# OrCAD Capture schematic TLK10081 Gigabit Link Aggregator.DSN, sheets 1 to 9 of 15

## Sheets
1 S15 BOARD TO BOARD CLOCK: size B
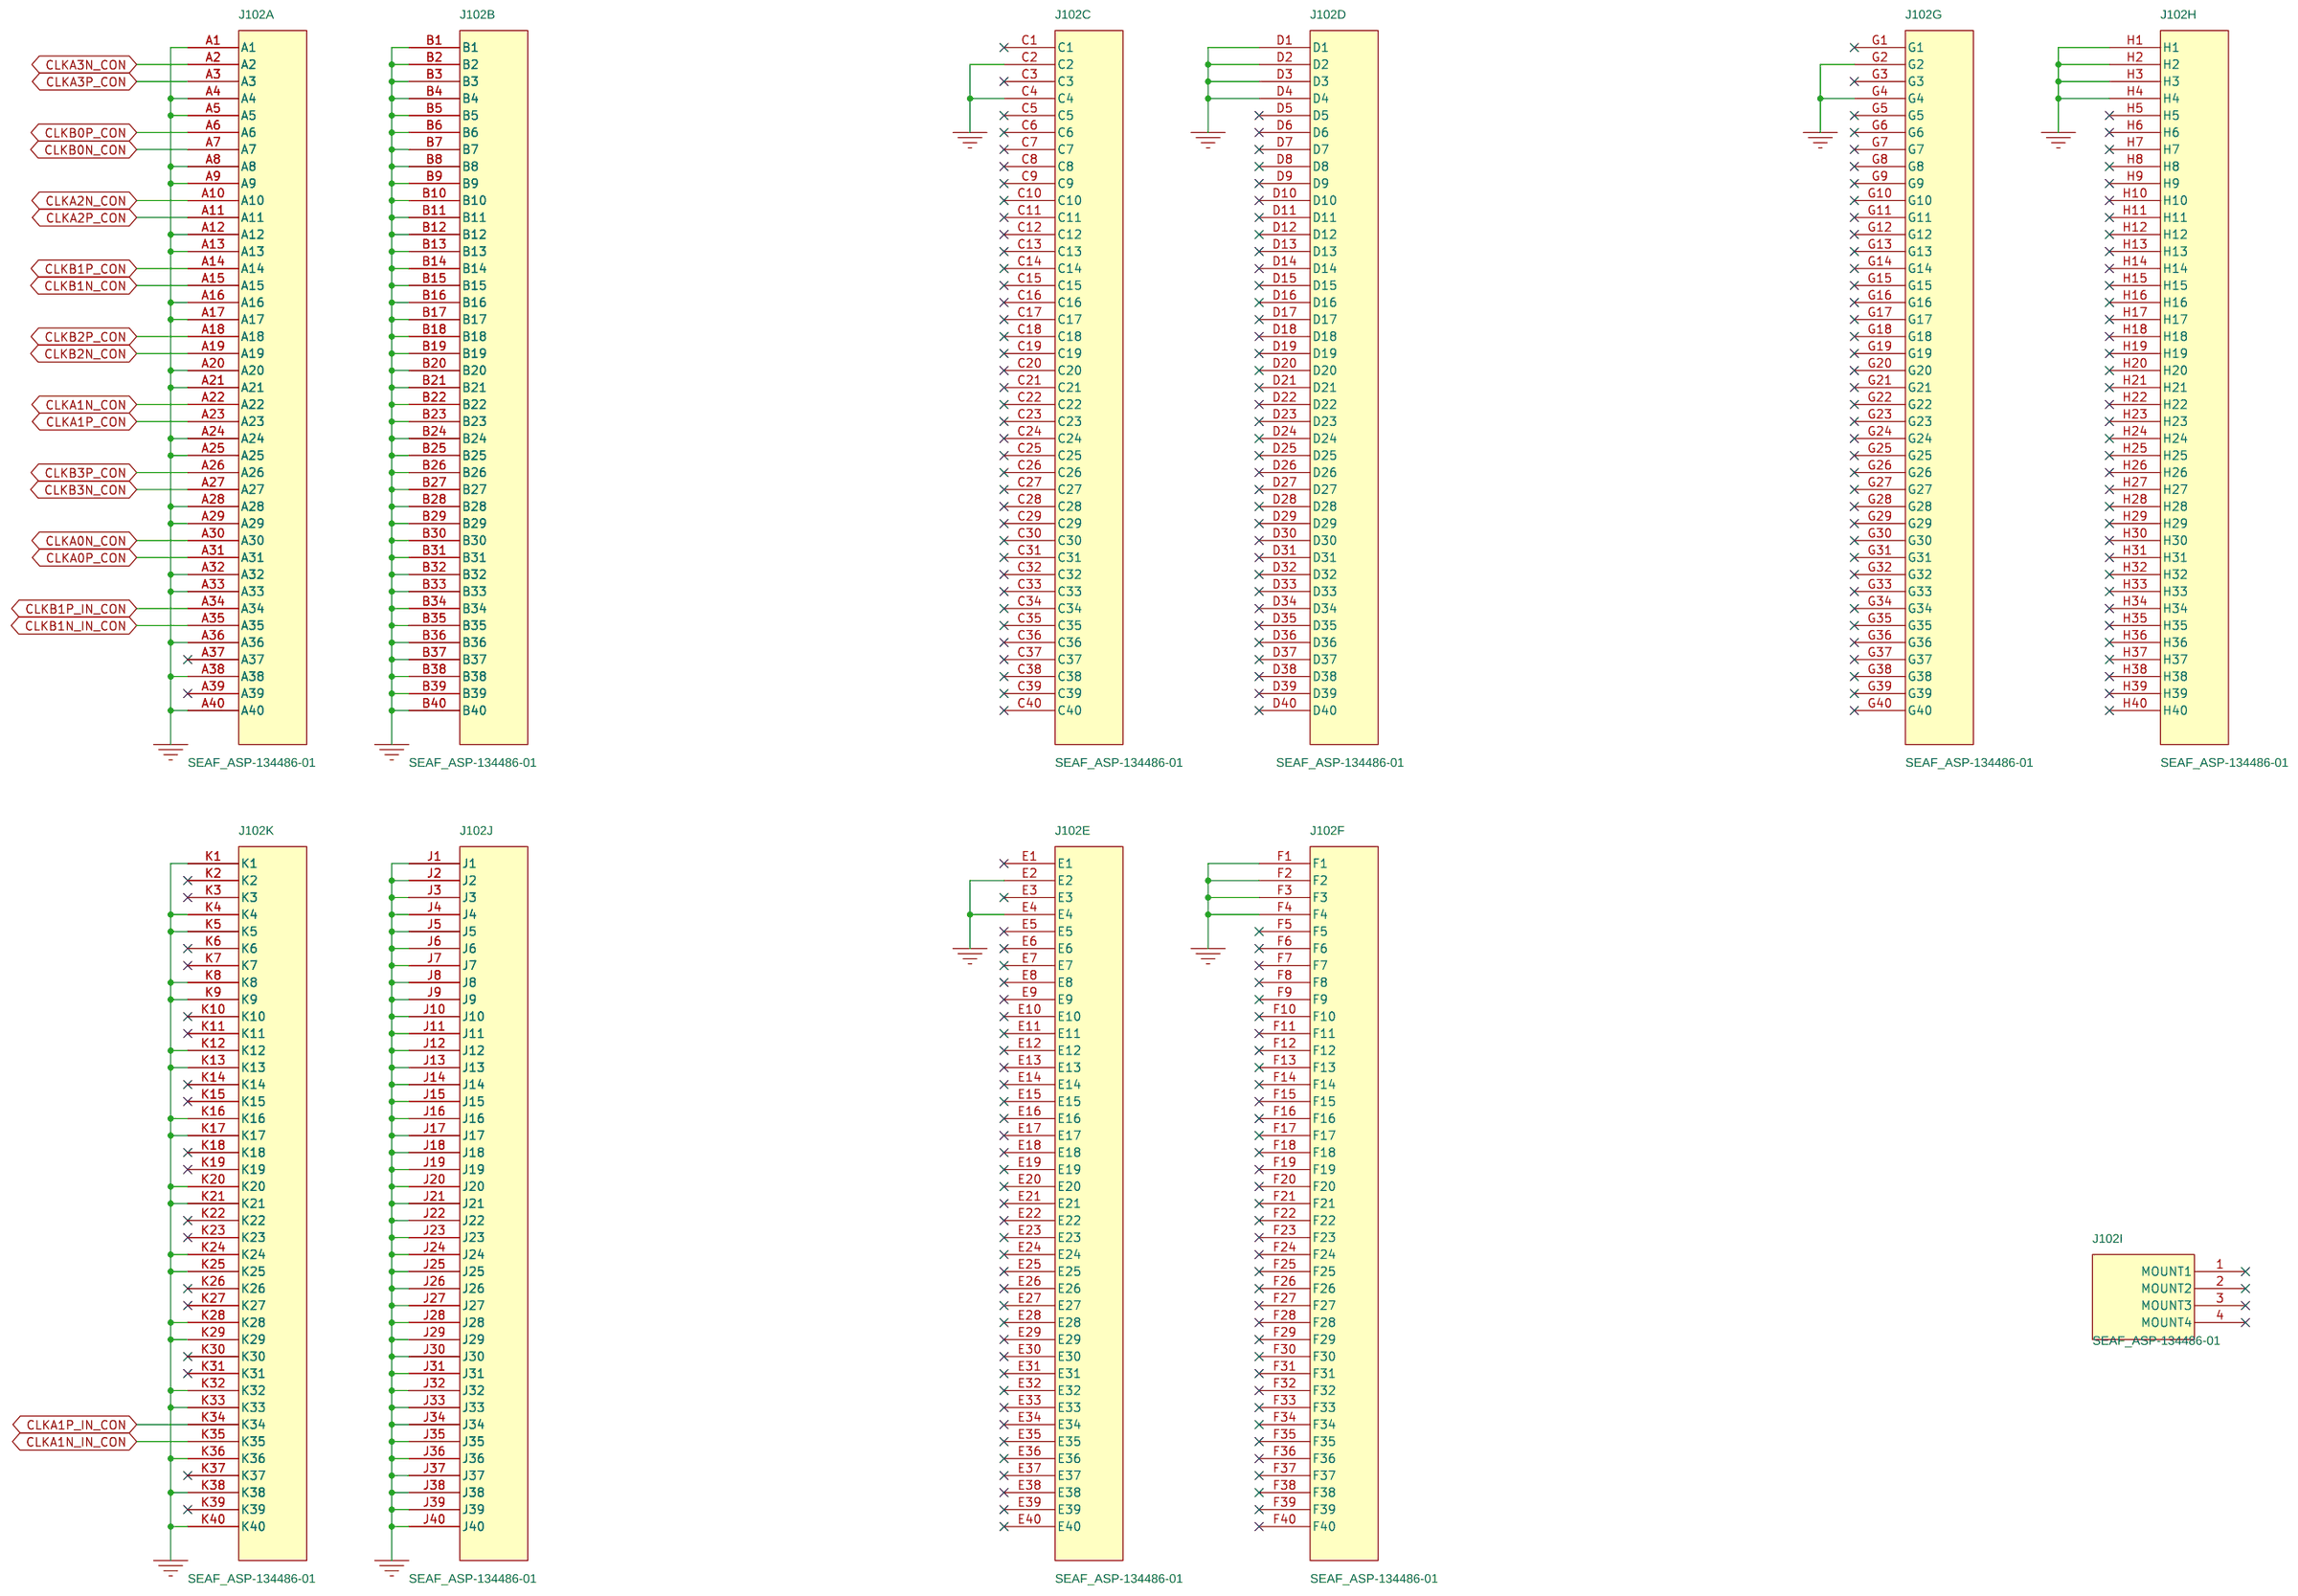
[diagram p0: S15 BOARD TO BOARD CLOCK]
2 S01 TLK10081 EVM COVER PAGE
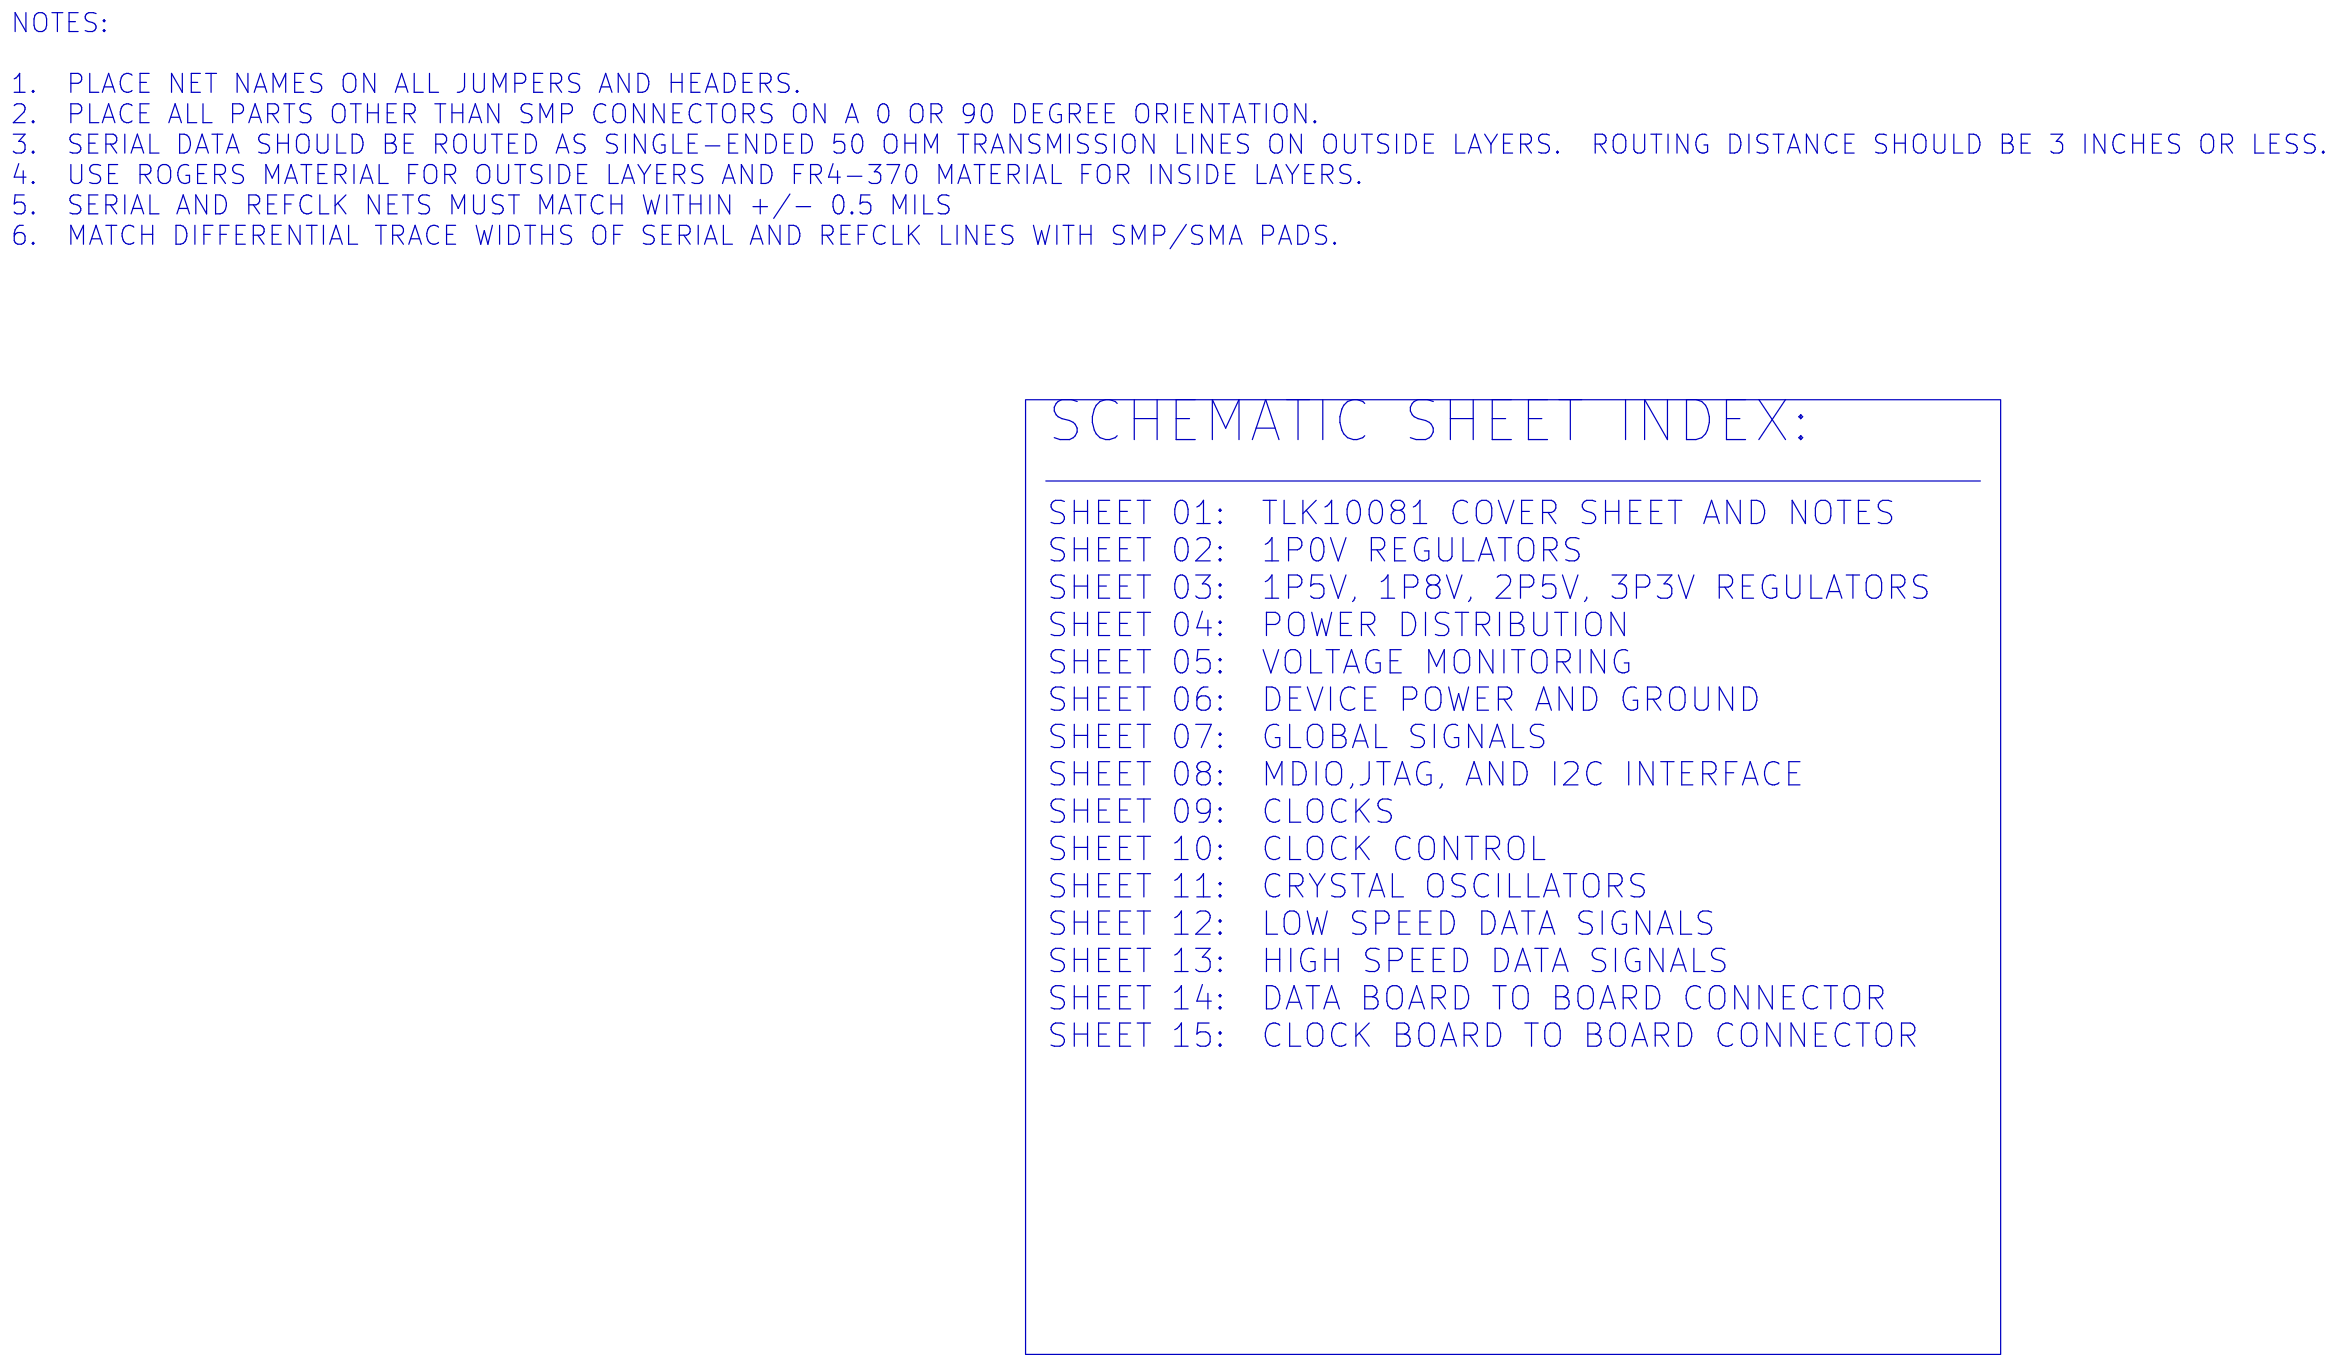
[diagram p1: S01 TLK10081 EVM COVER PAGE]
3 S02 1P0V REGULATORS: size B
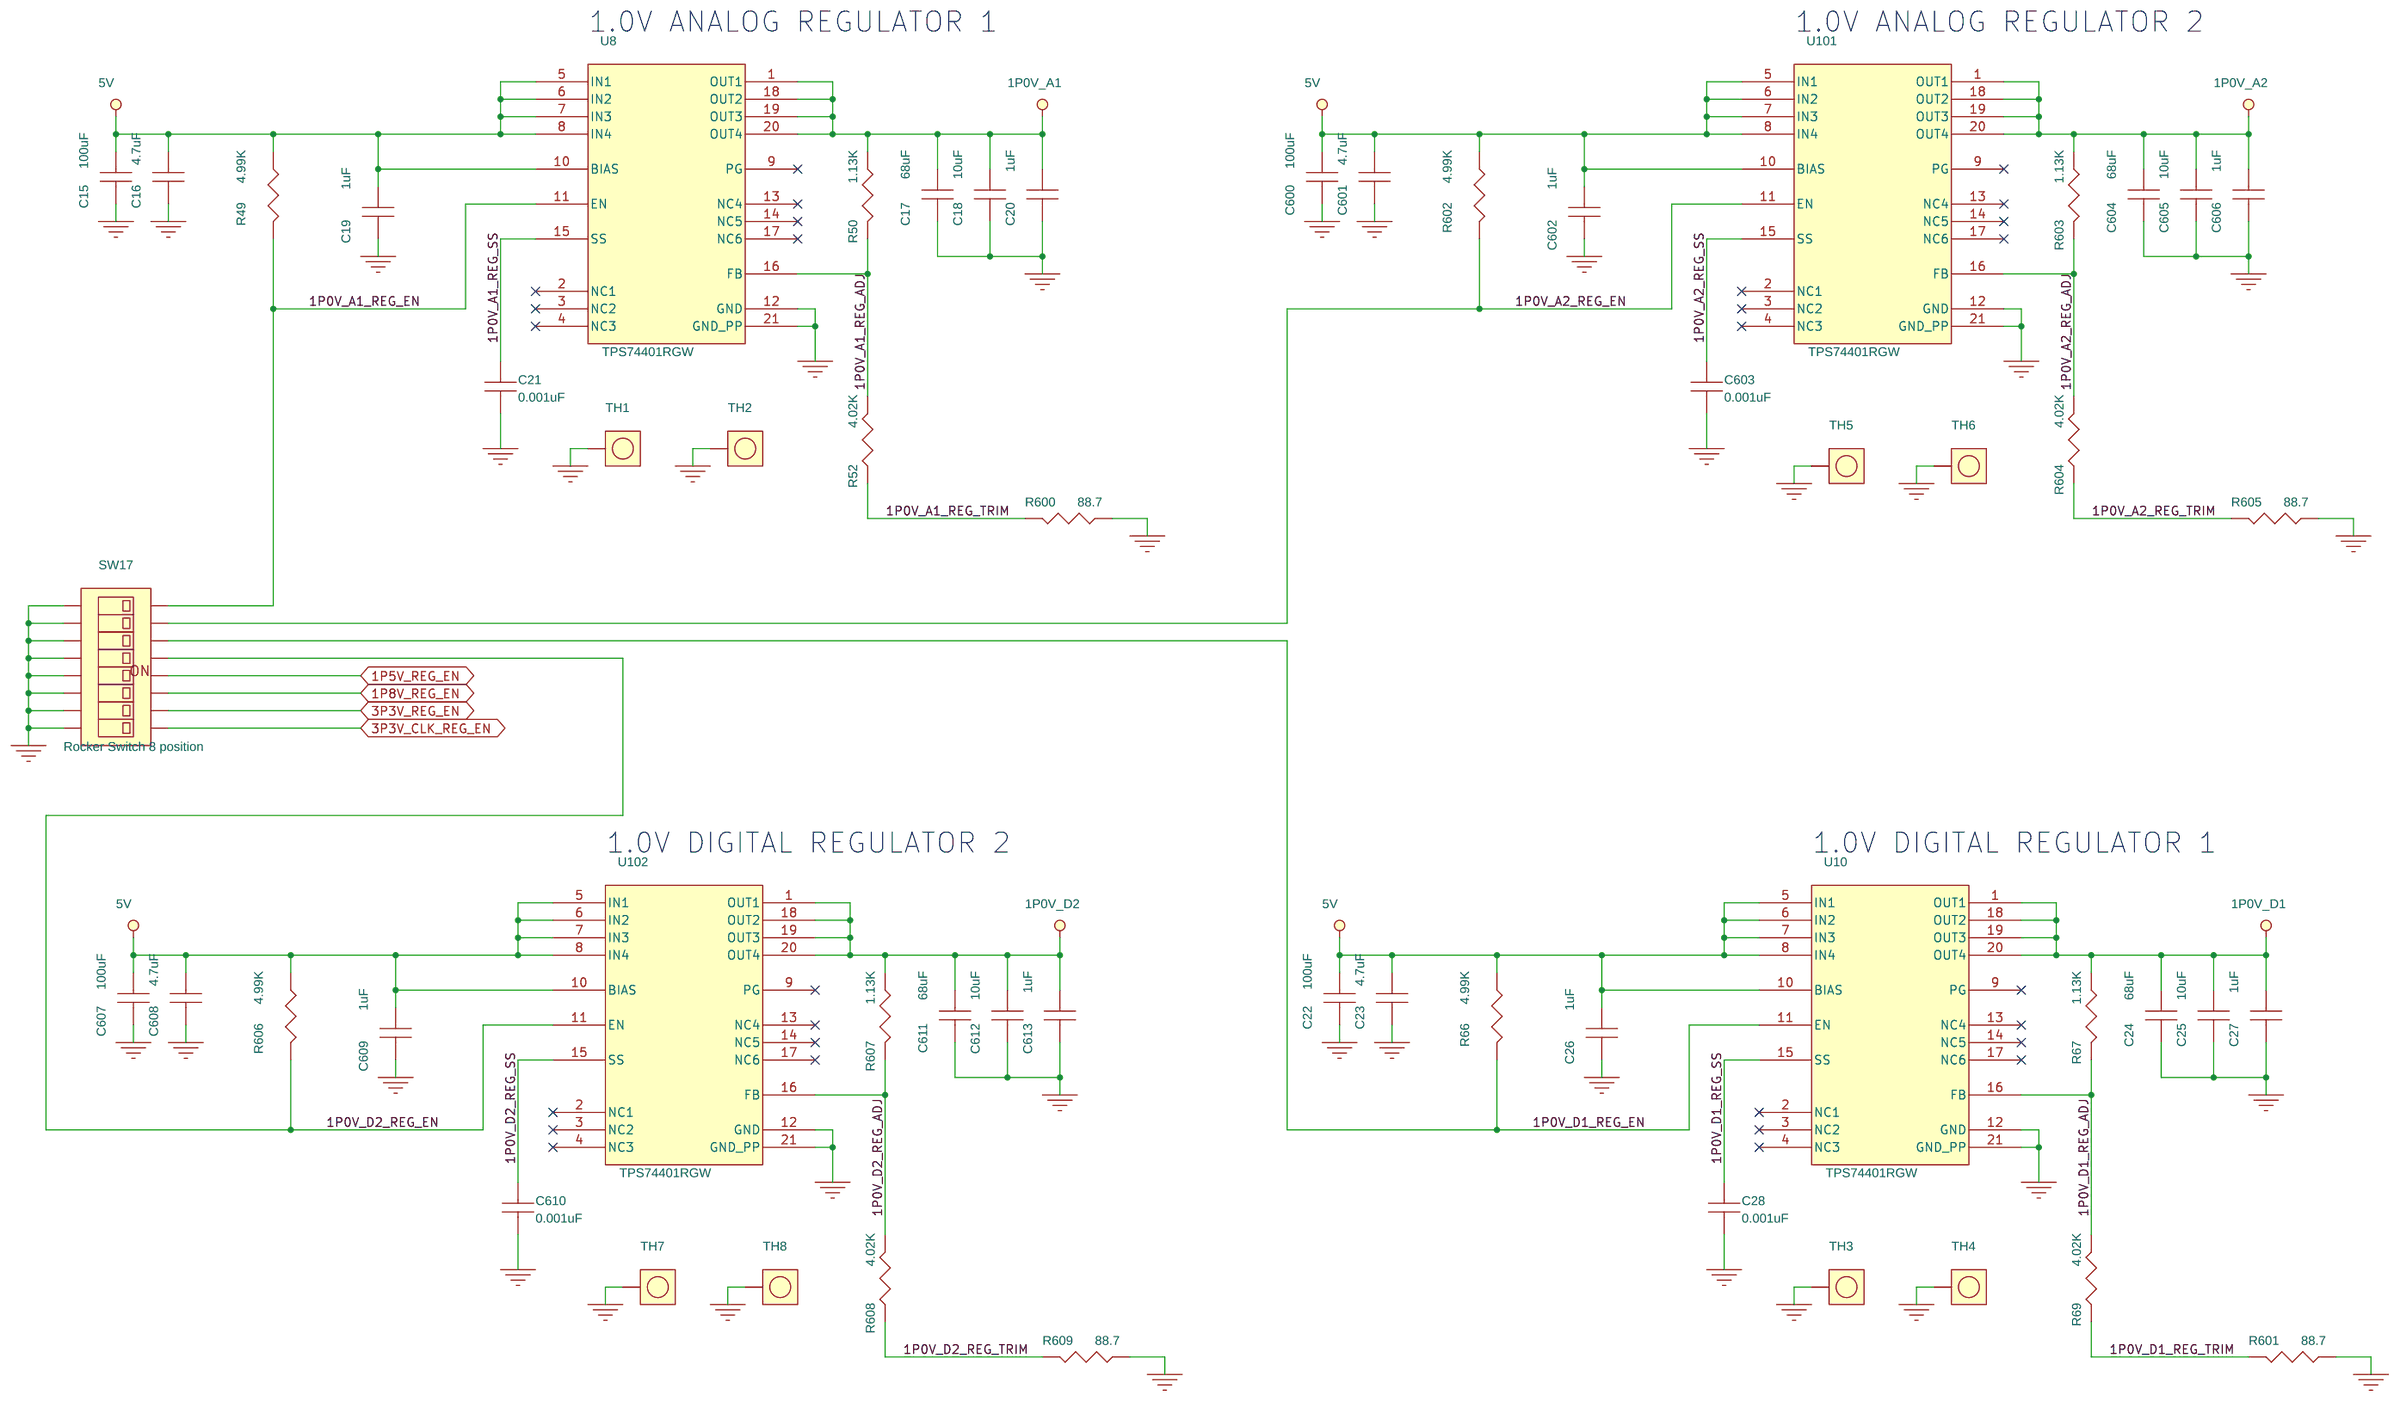
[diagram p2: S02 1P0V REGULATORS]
4 S03 1P5,1P8,2P5,3P3V REGULATORS: size B
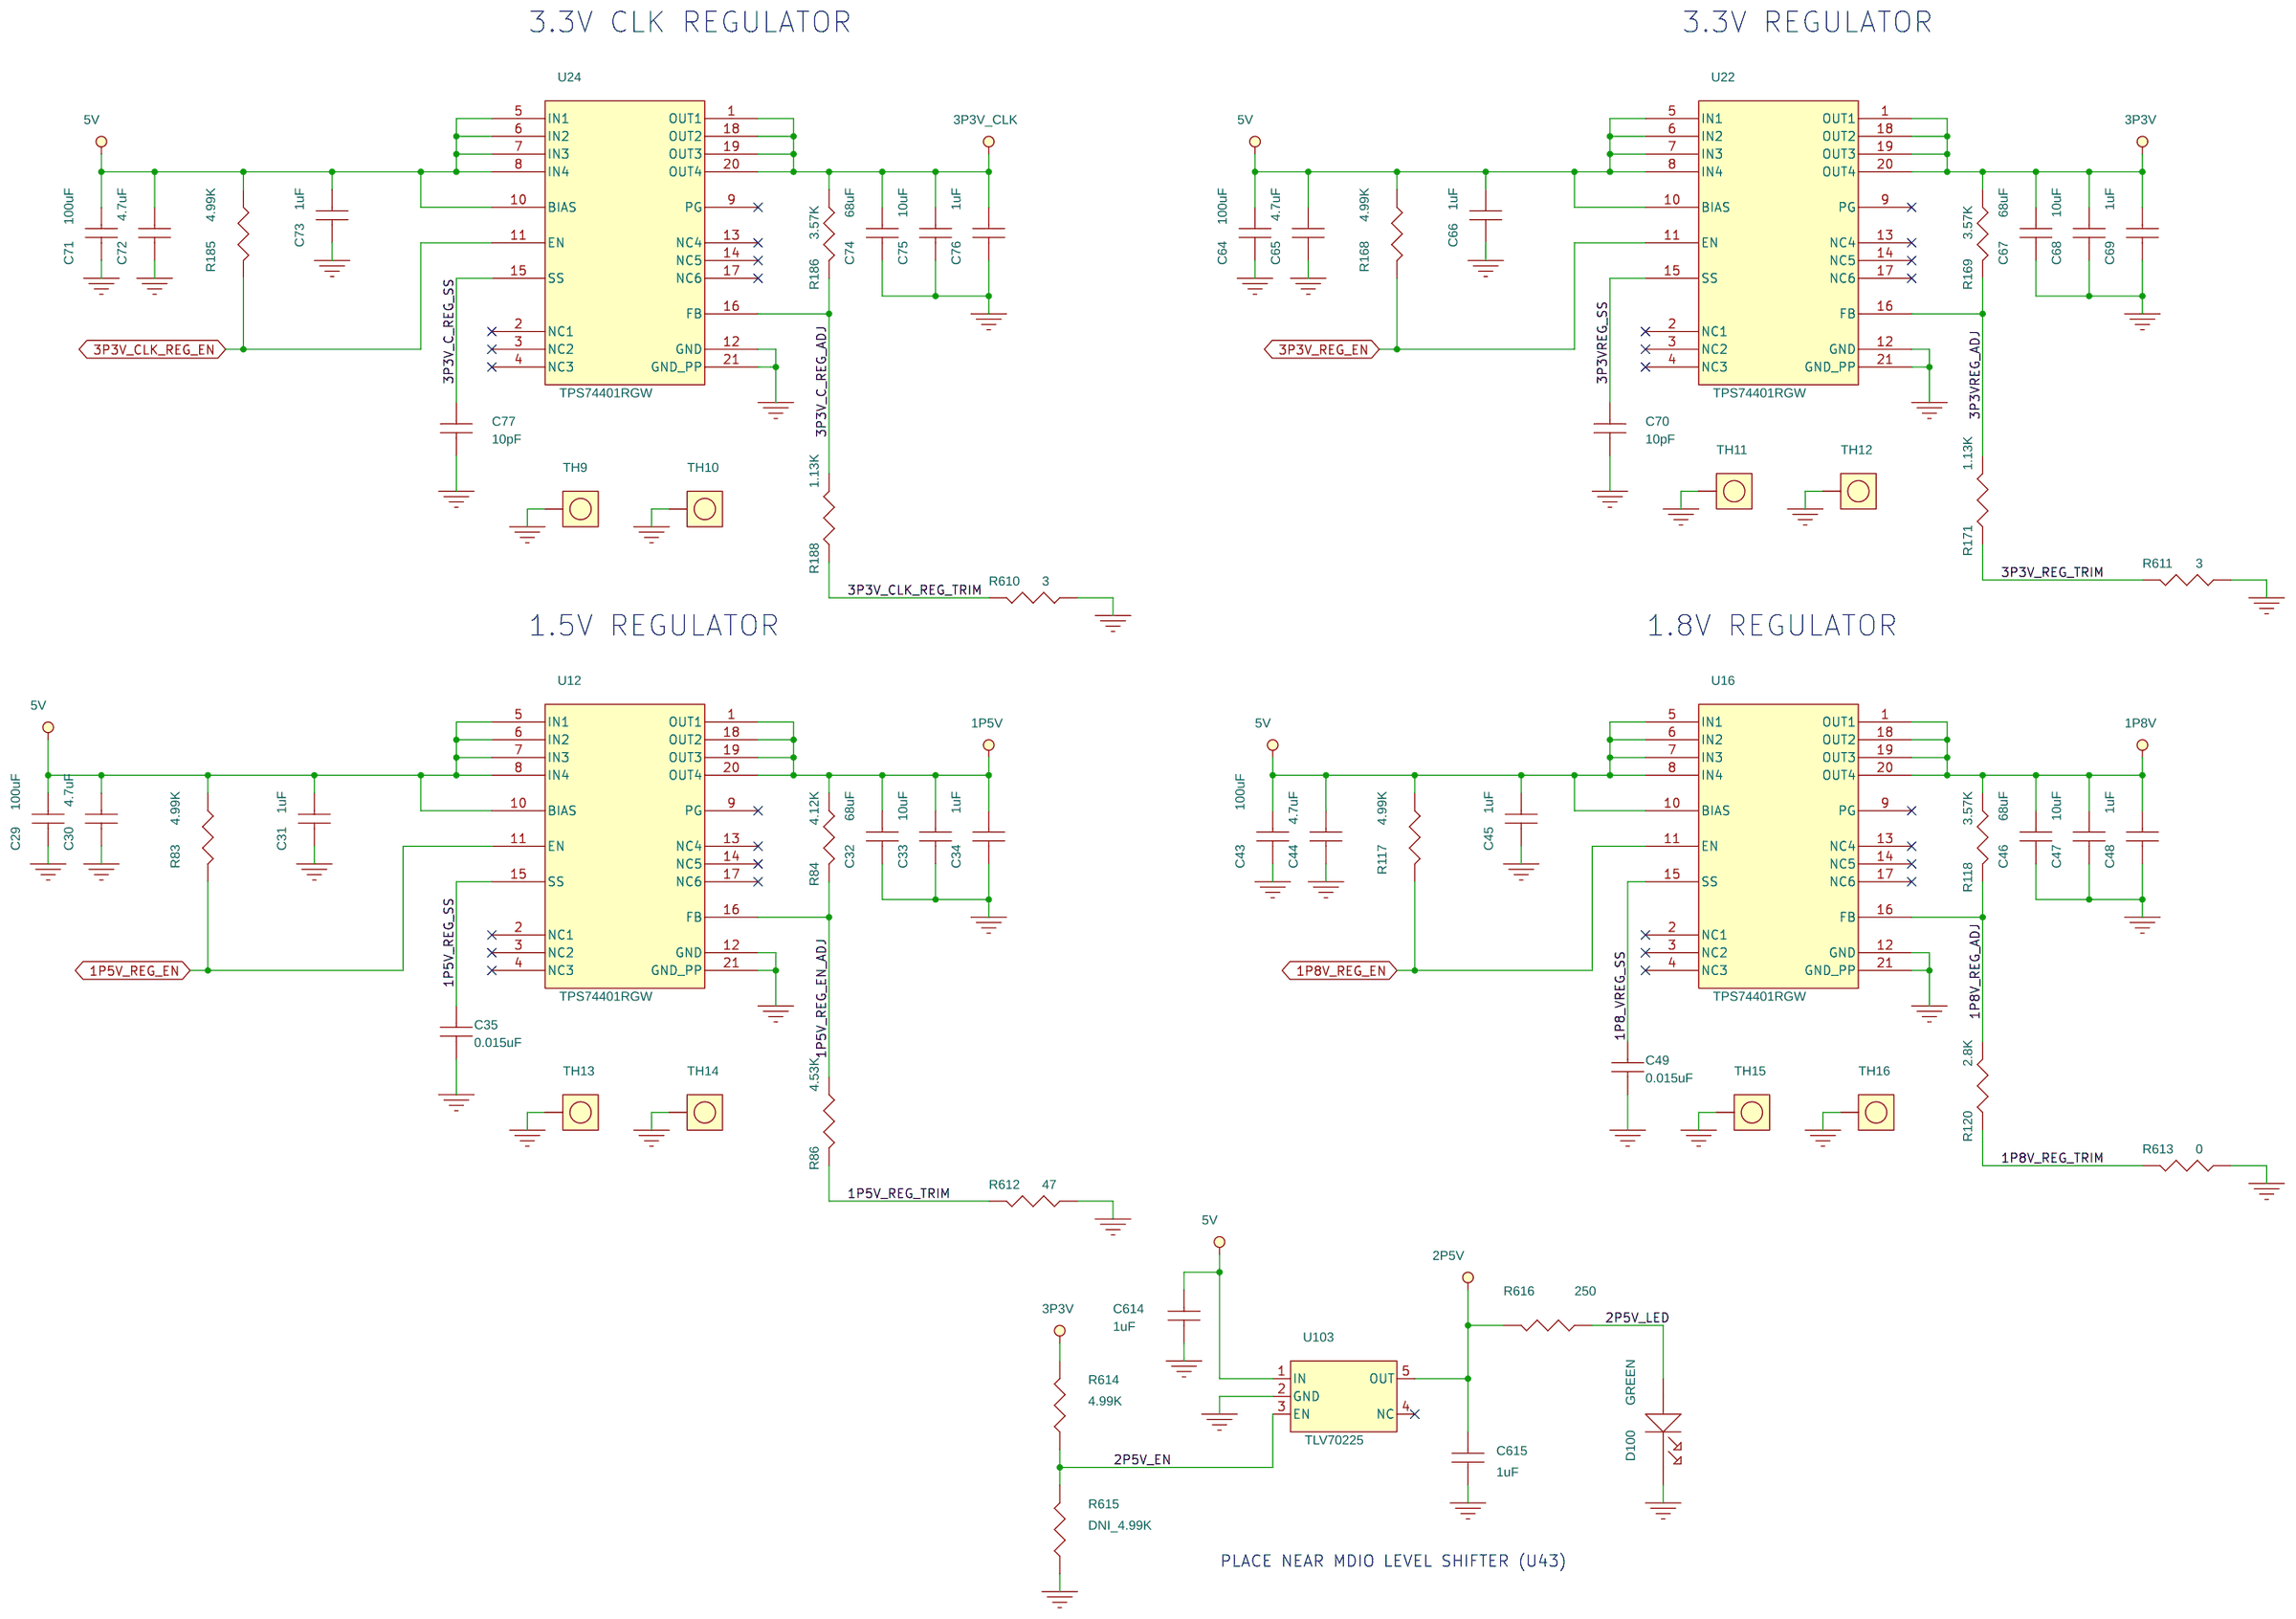
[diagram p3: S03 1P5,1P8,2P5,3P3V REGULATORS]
5 S04 POWER DISTRIBUTION: size B
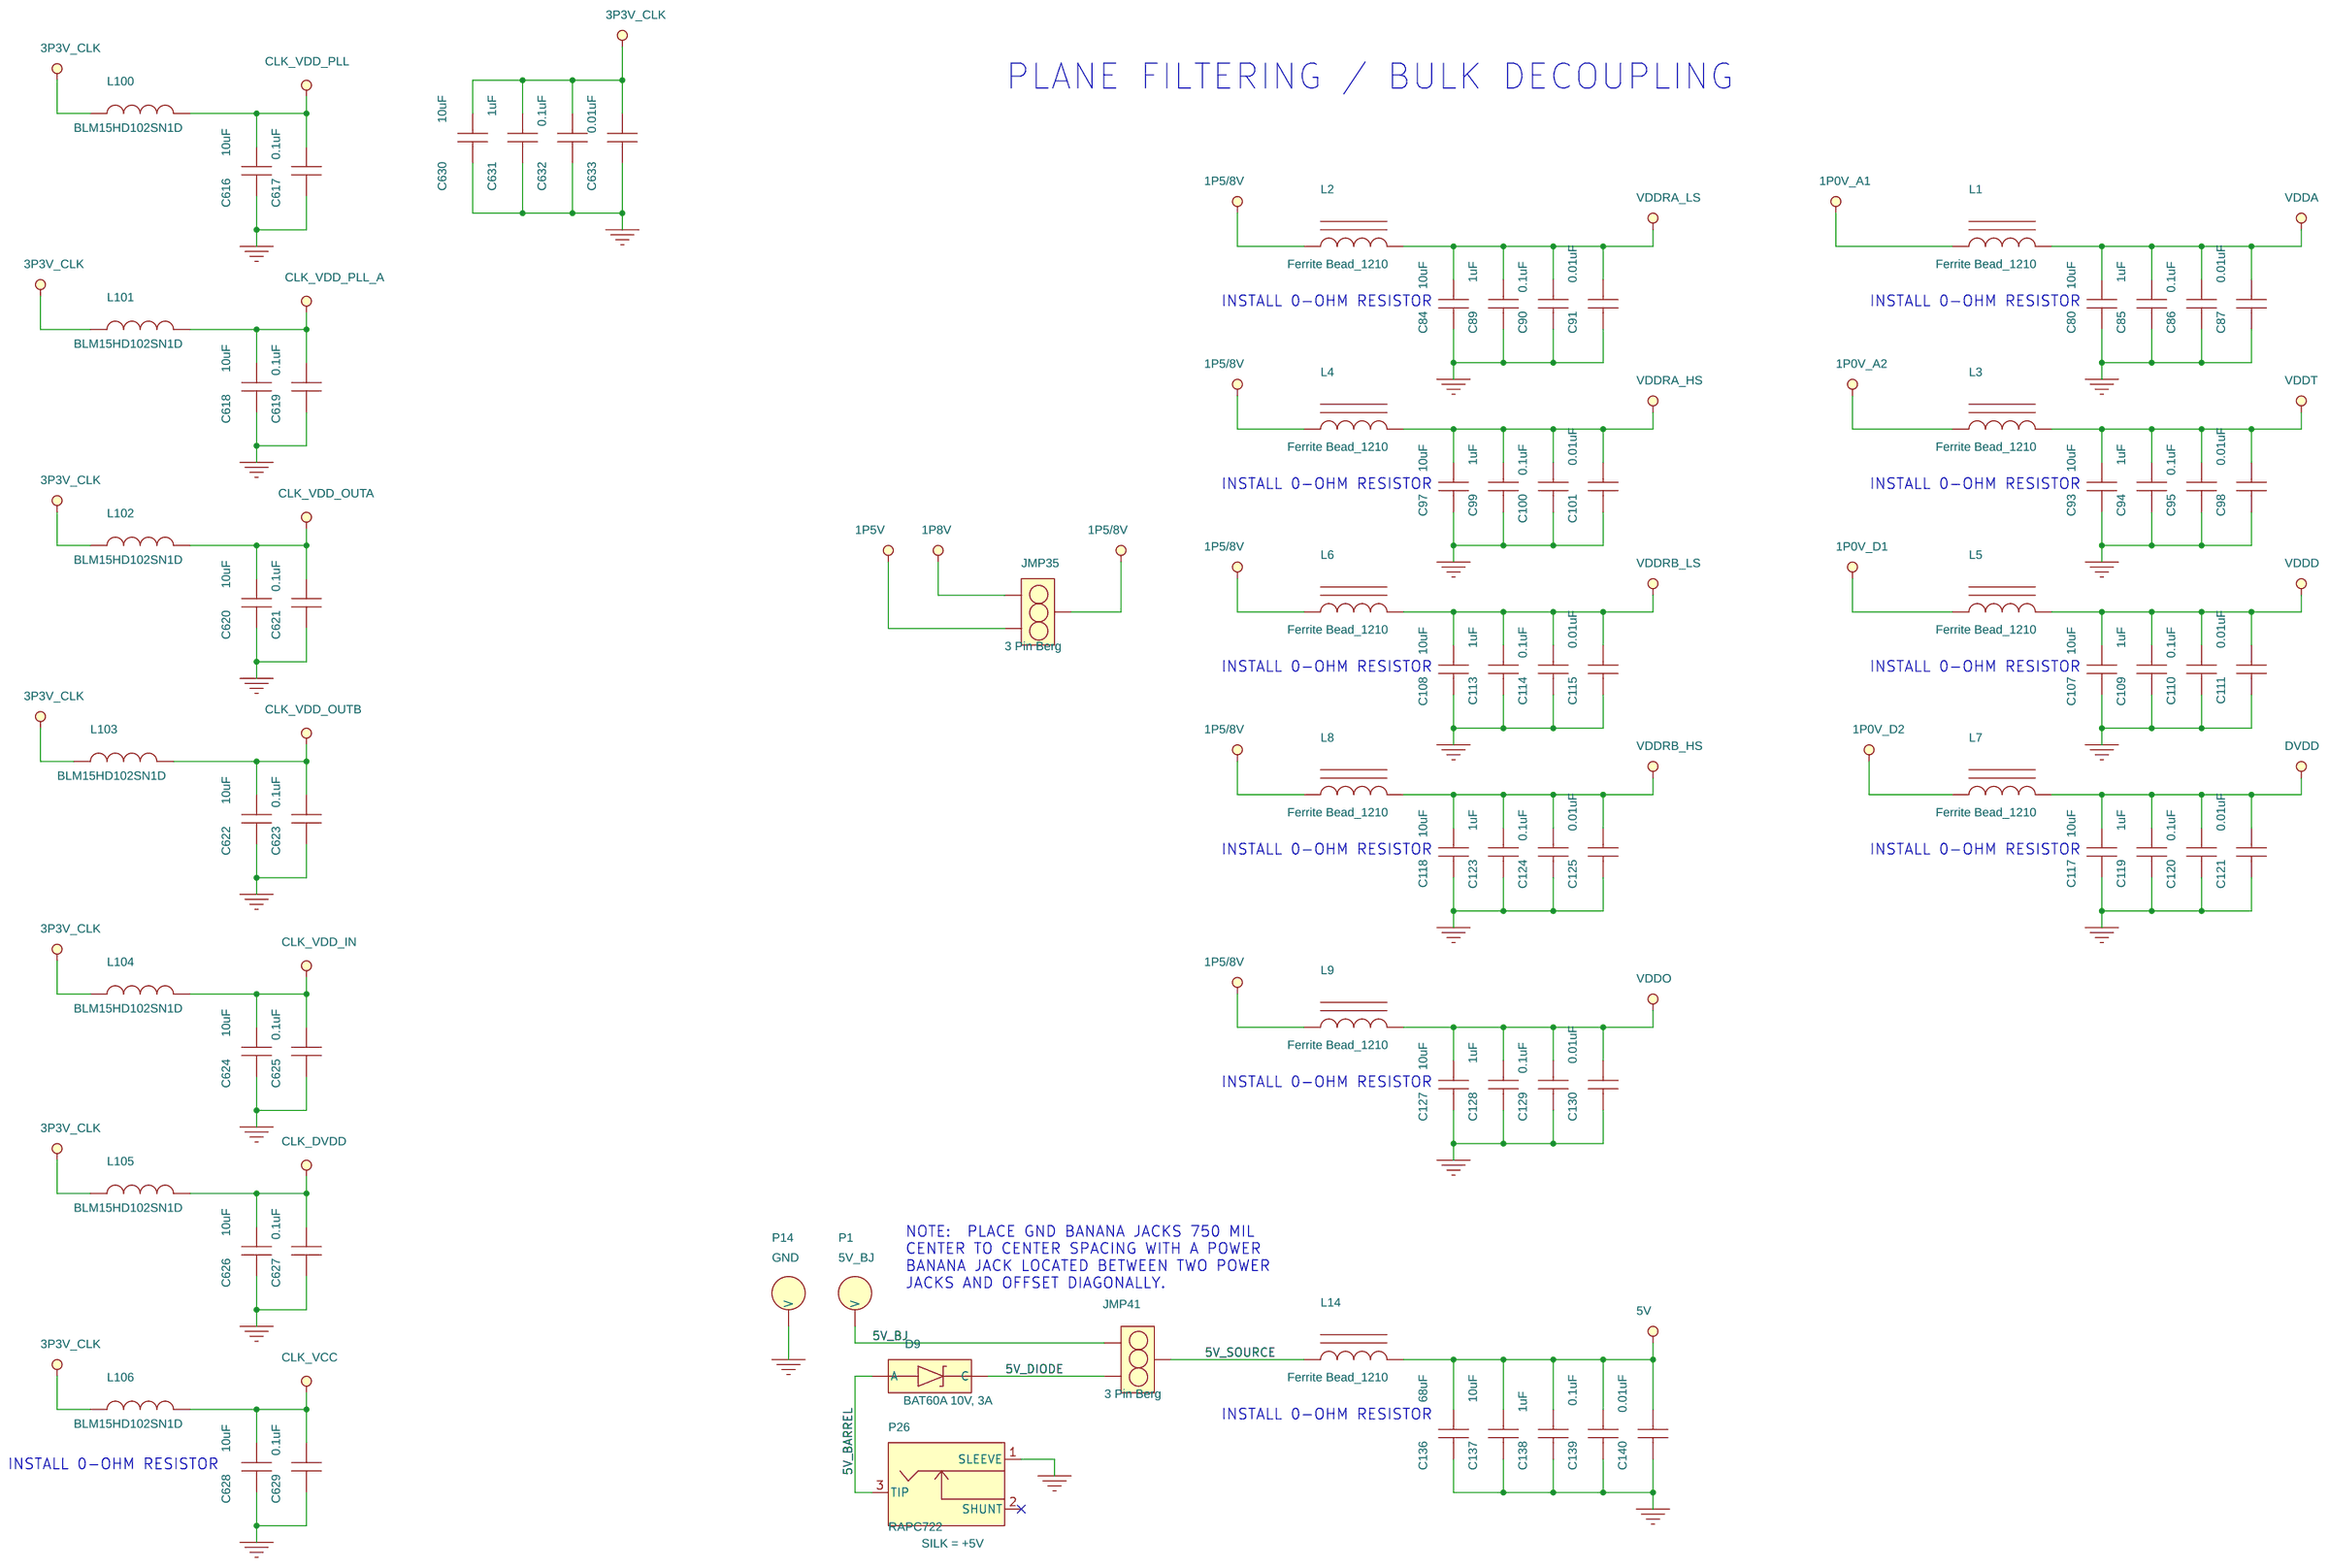
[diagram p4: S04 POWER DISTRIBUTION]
6 S06 DEVICE POWER GROUND: size B
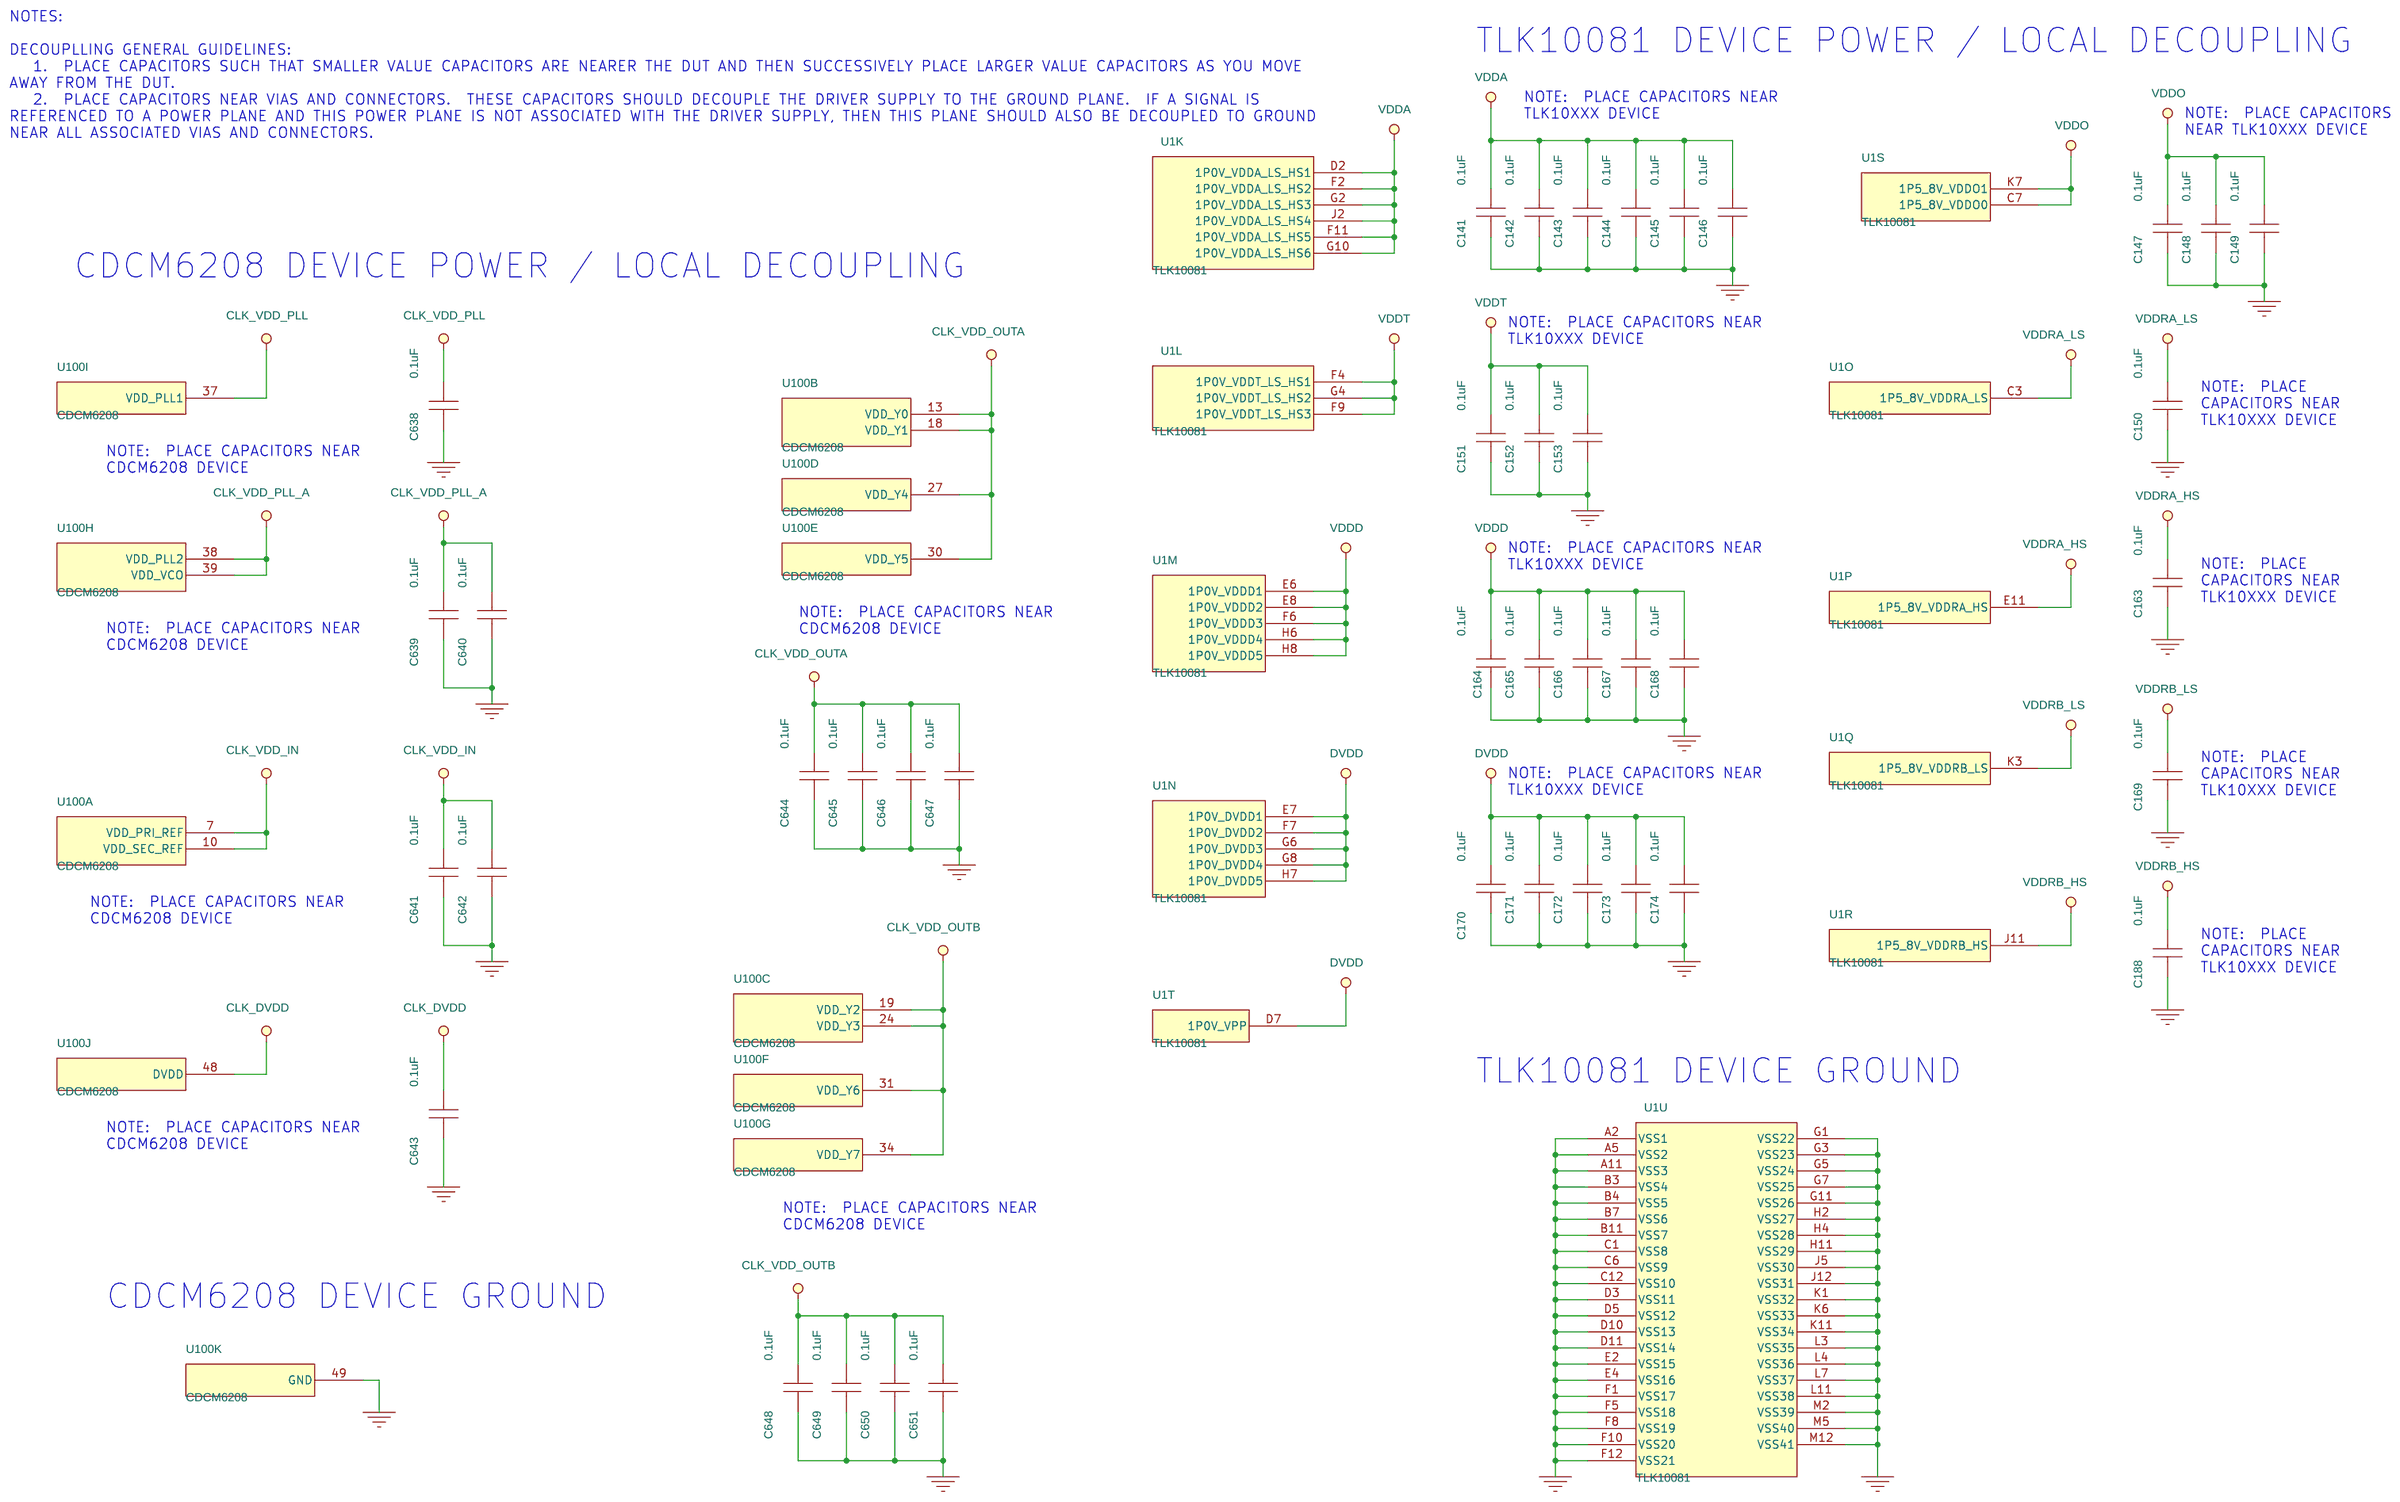
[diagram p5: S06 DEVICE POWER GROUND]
7 S07 GLOBAL SIGNALS: size B
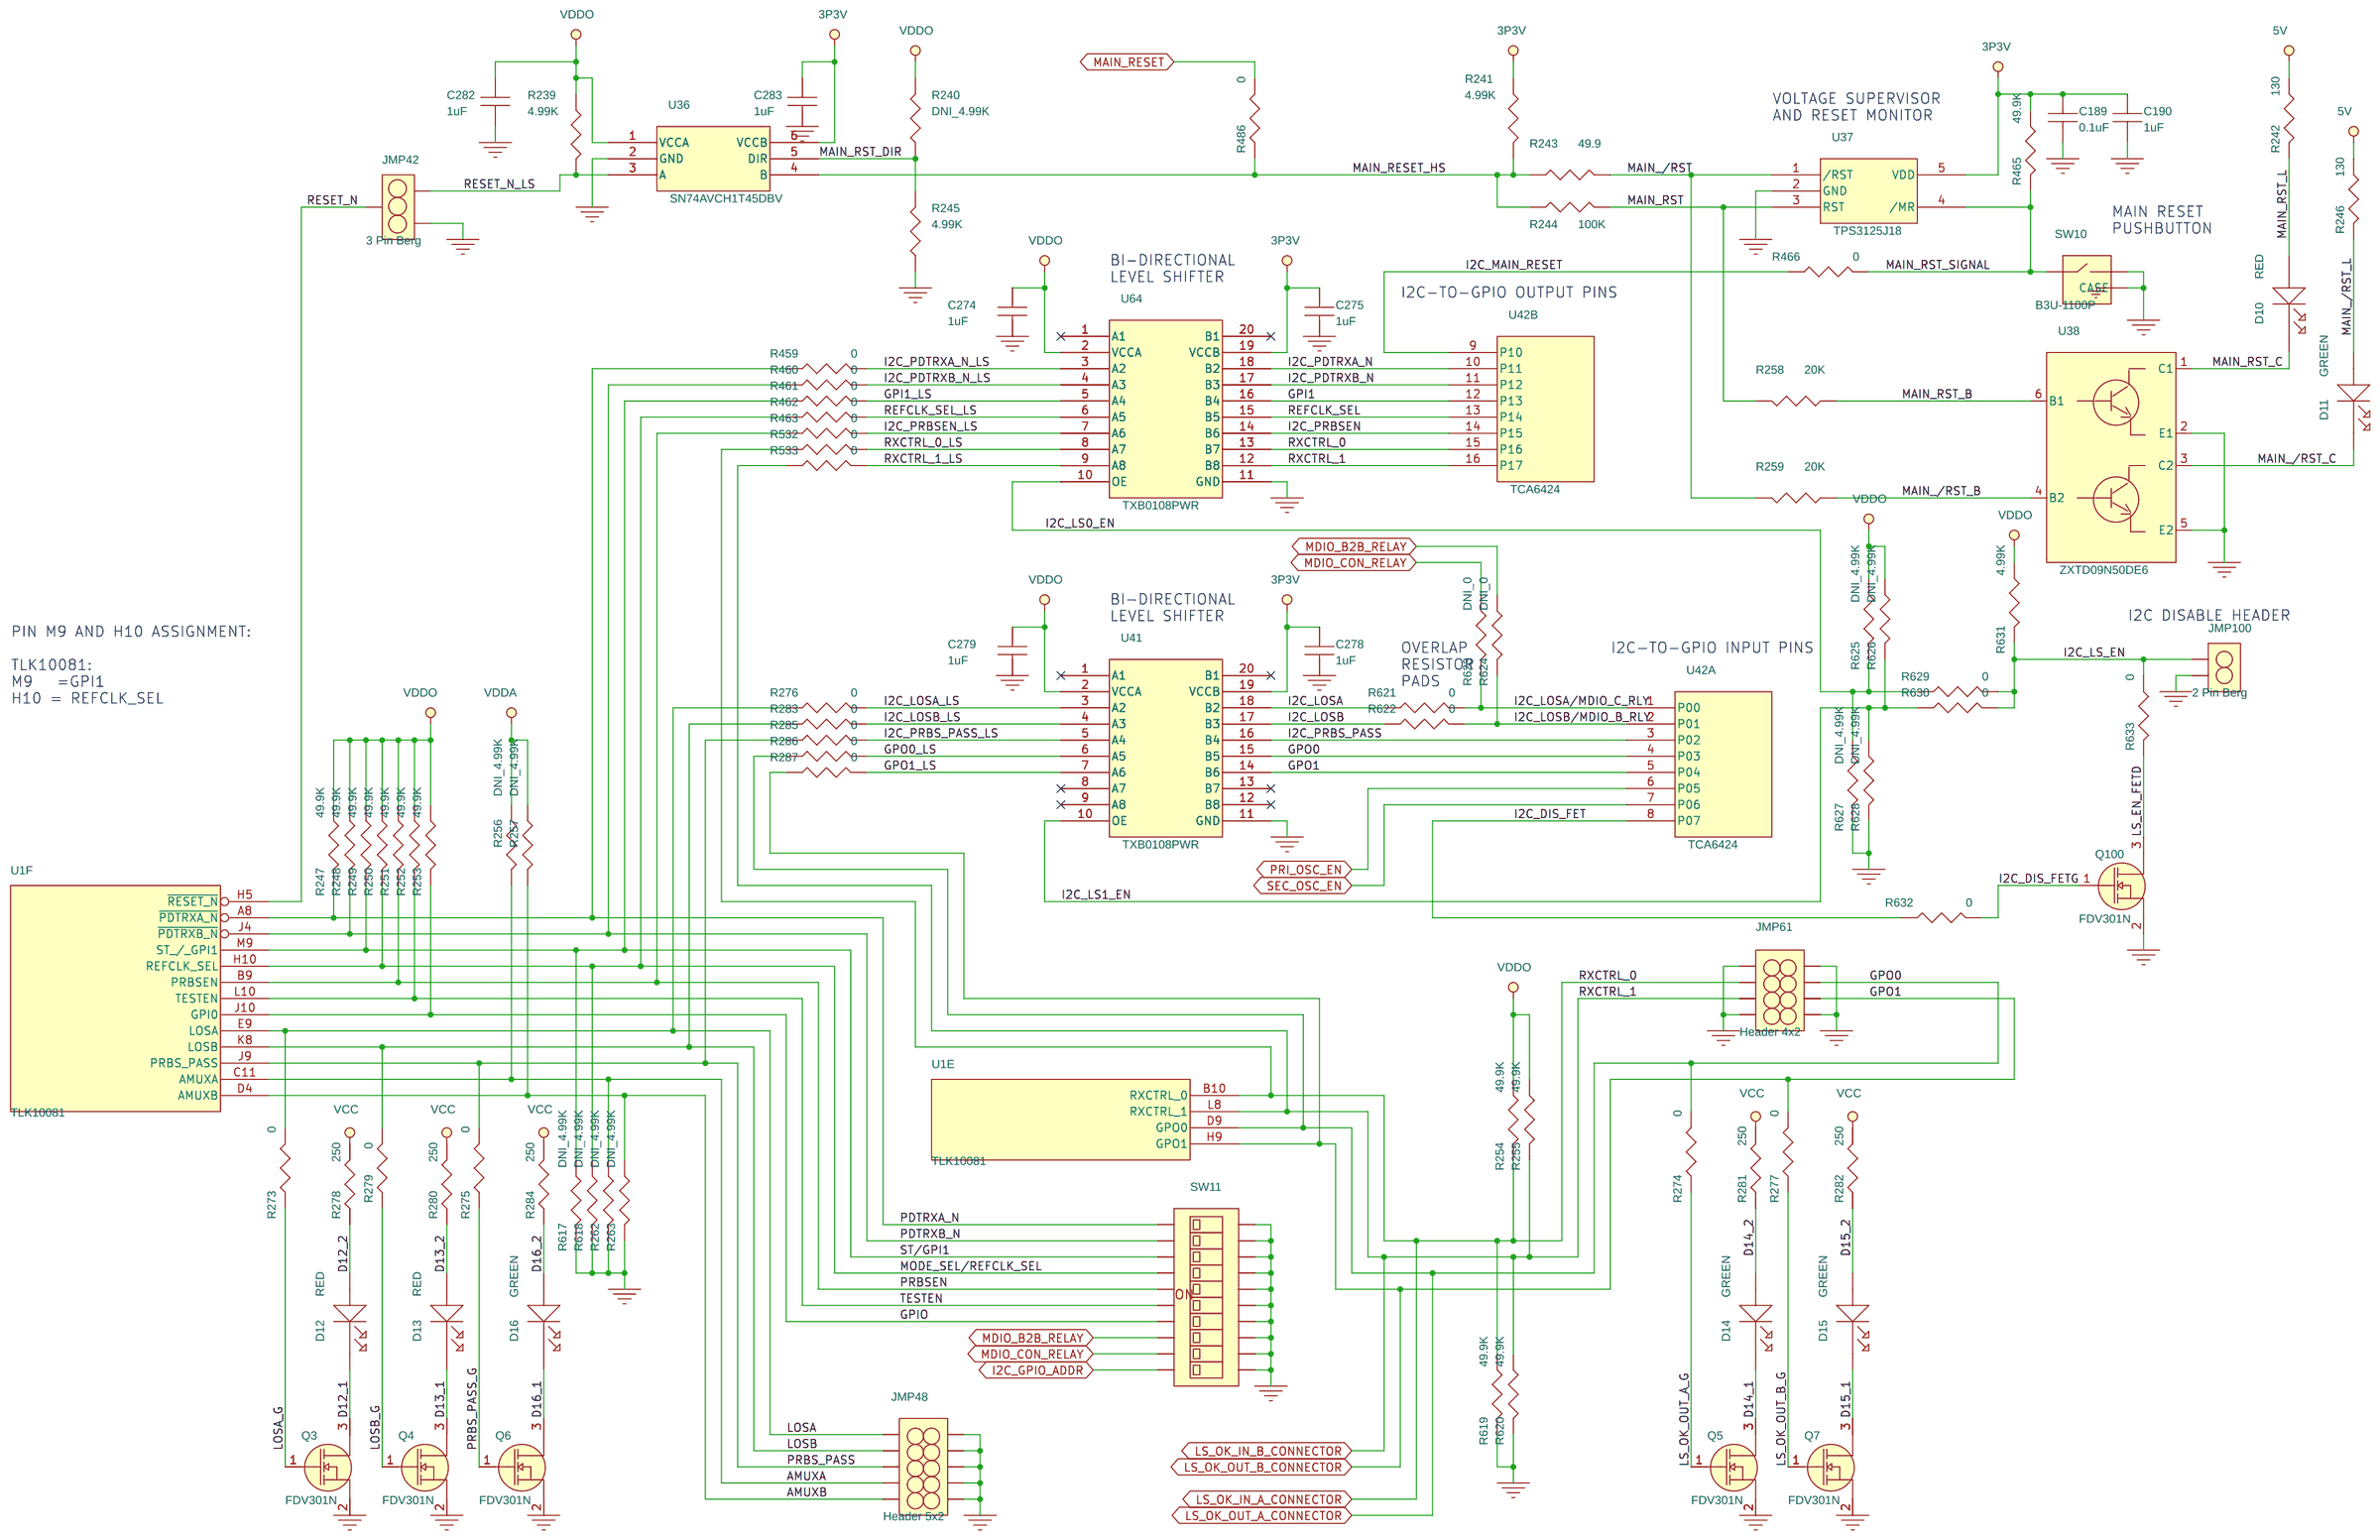
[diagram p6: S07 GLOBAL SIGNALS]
8 S08 MDIO, JTAG, I2C INTERFACE: size B
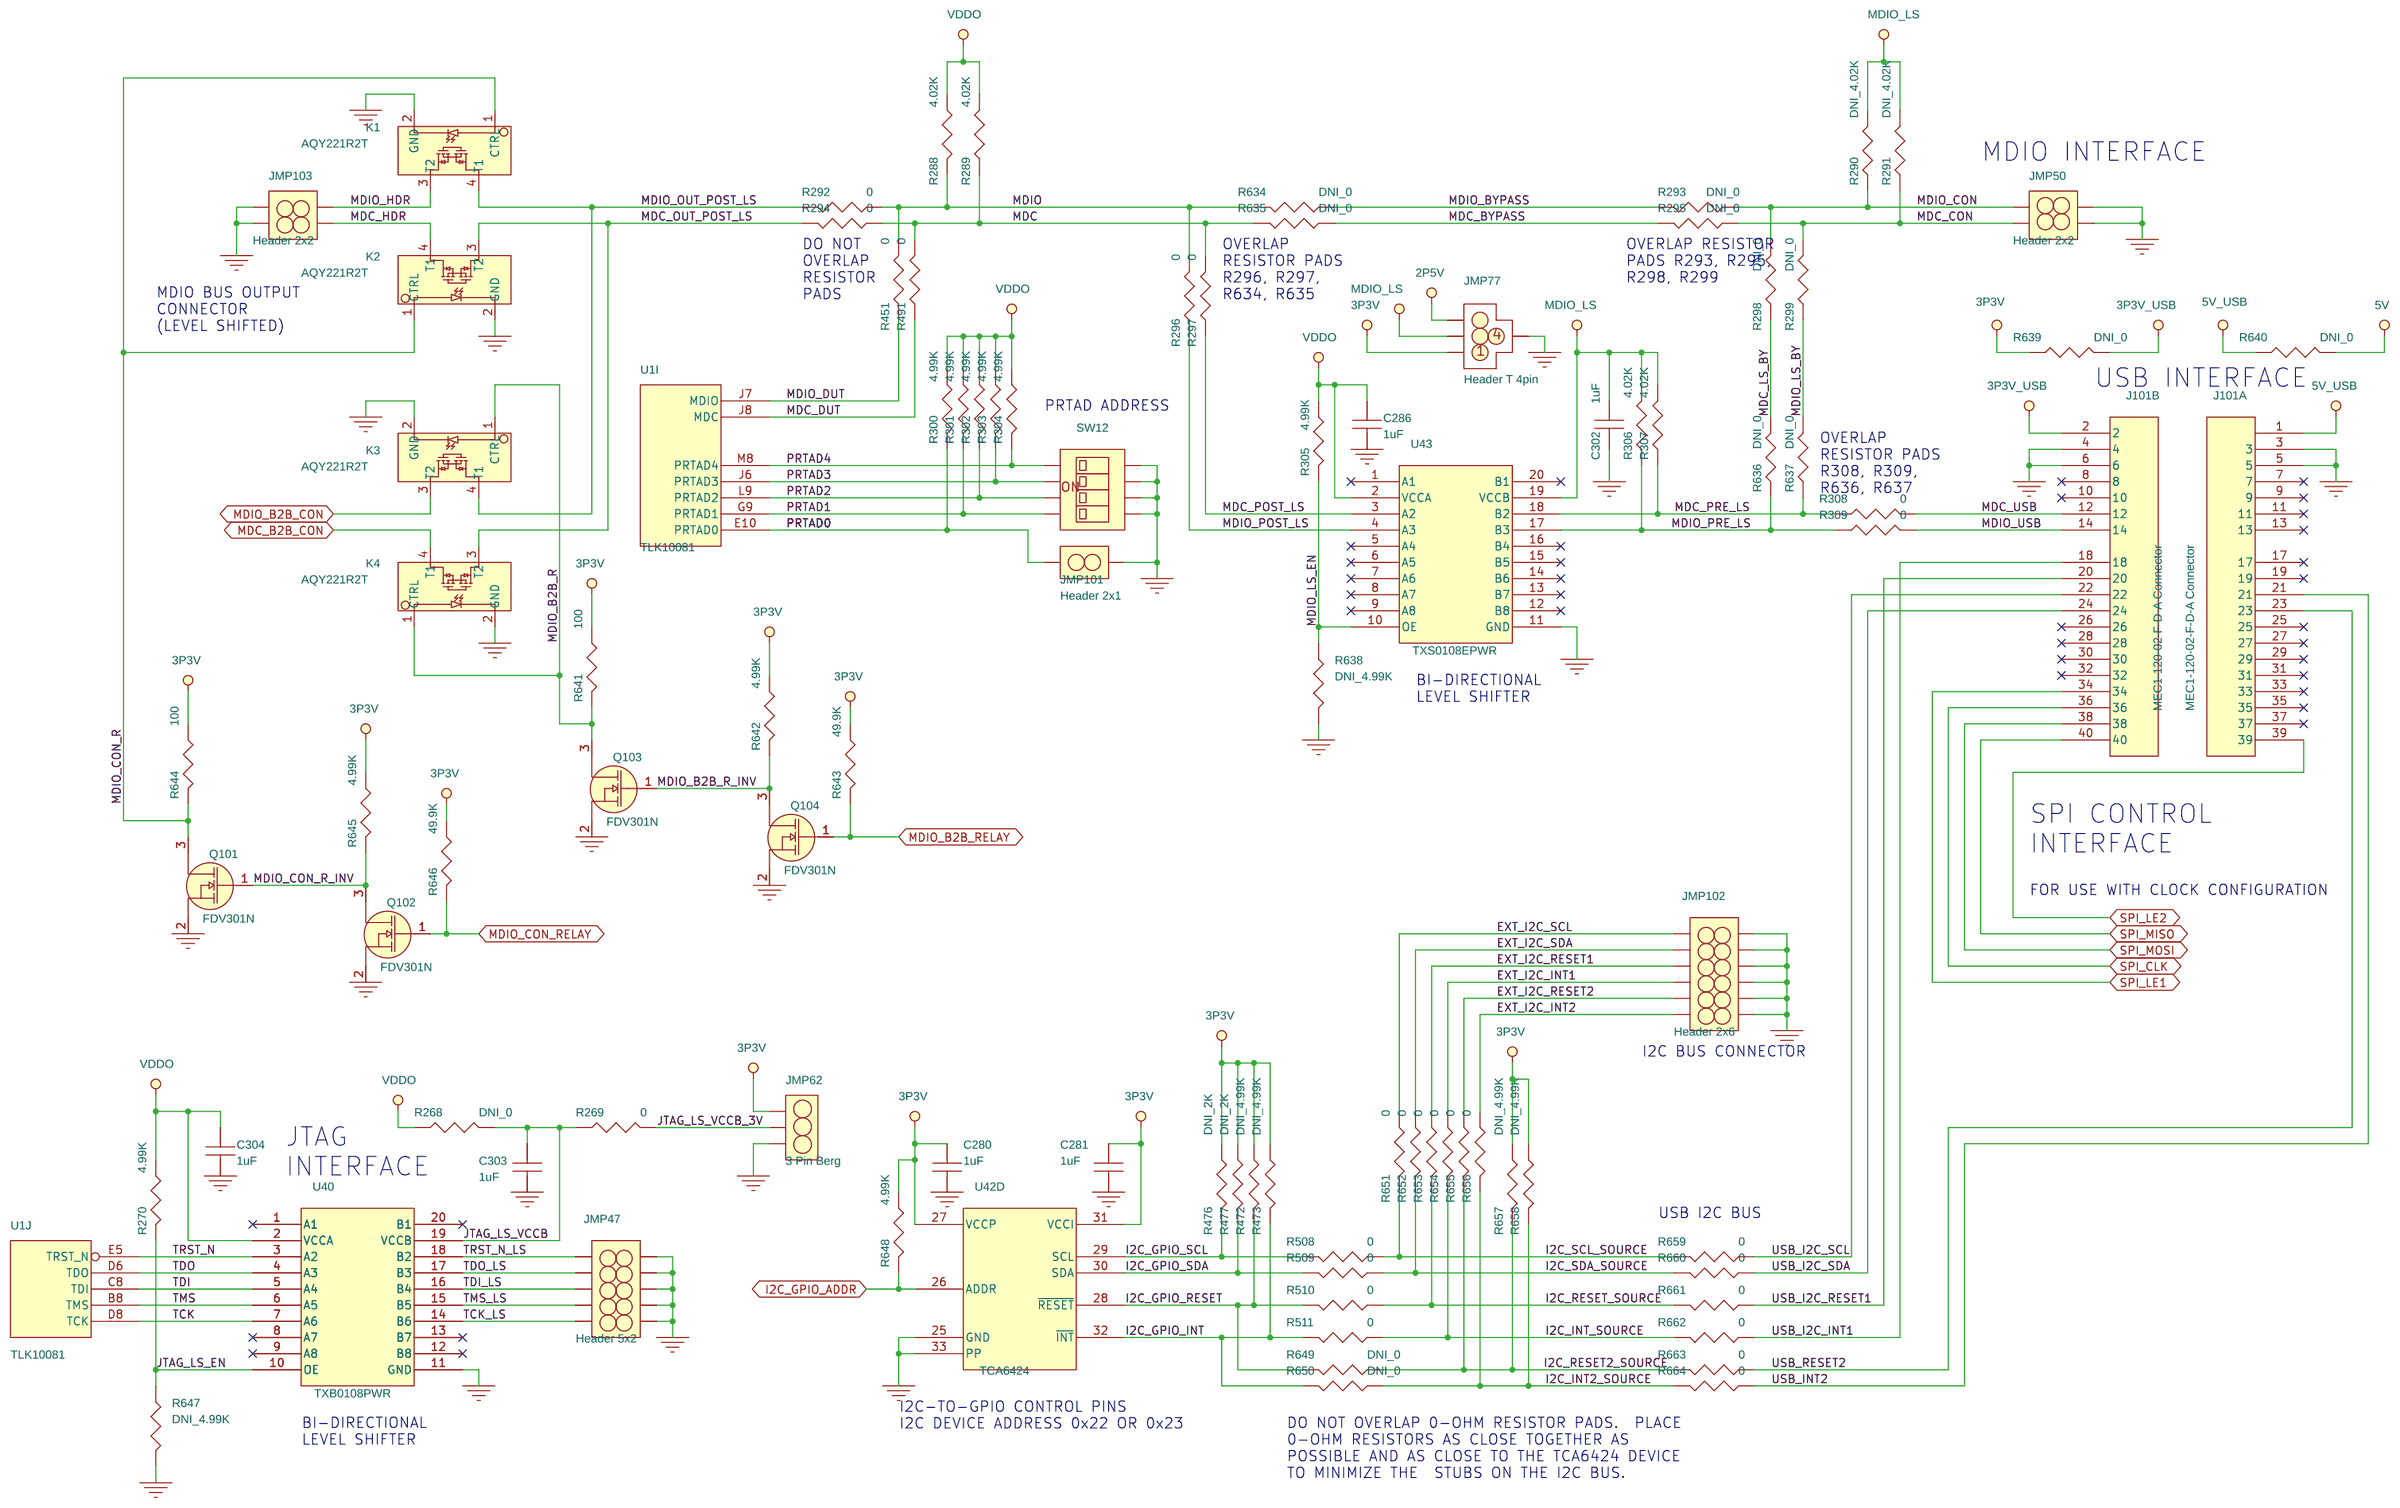
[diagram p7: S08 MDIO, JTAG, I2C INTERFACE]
9 S09 CLOCKS: size B
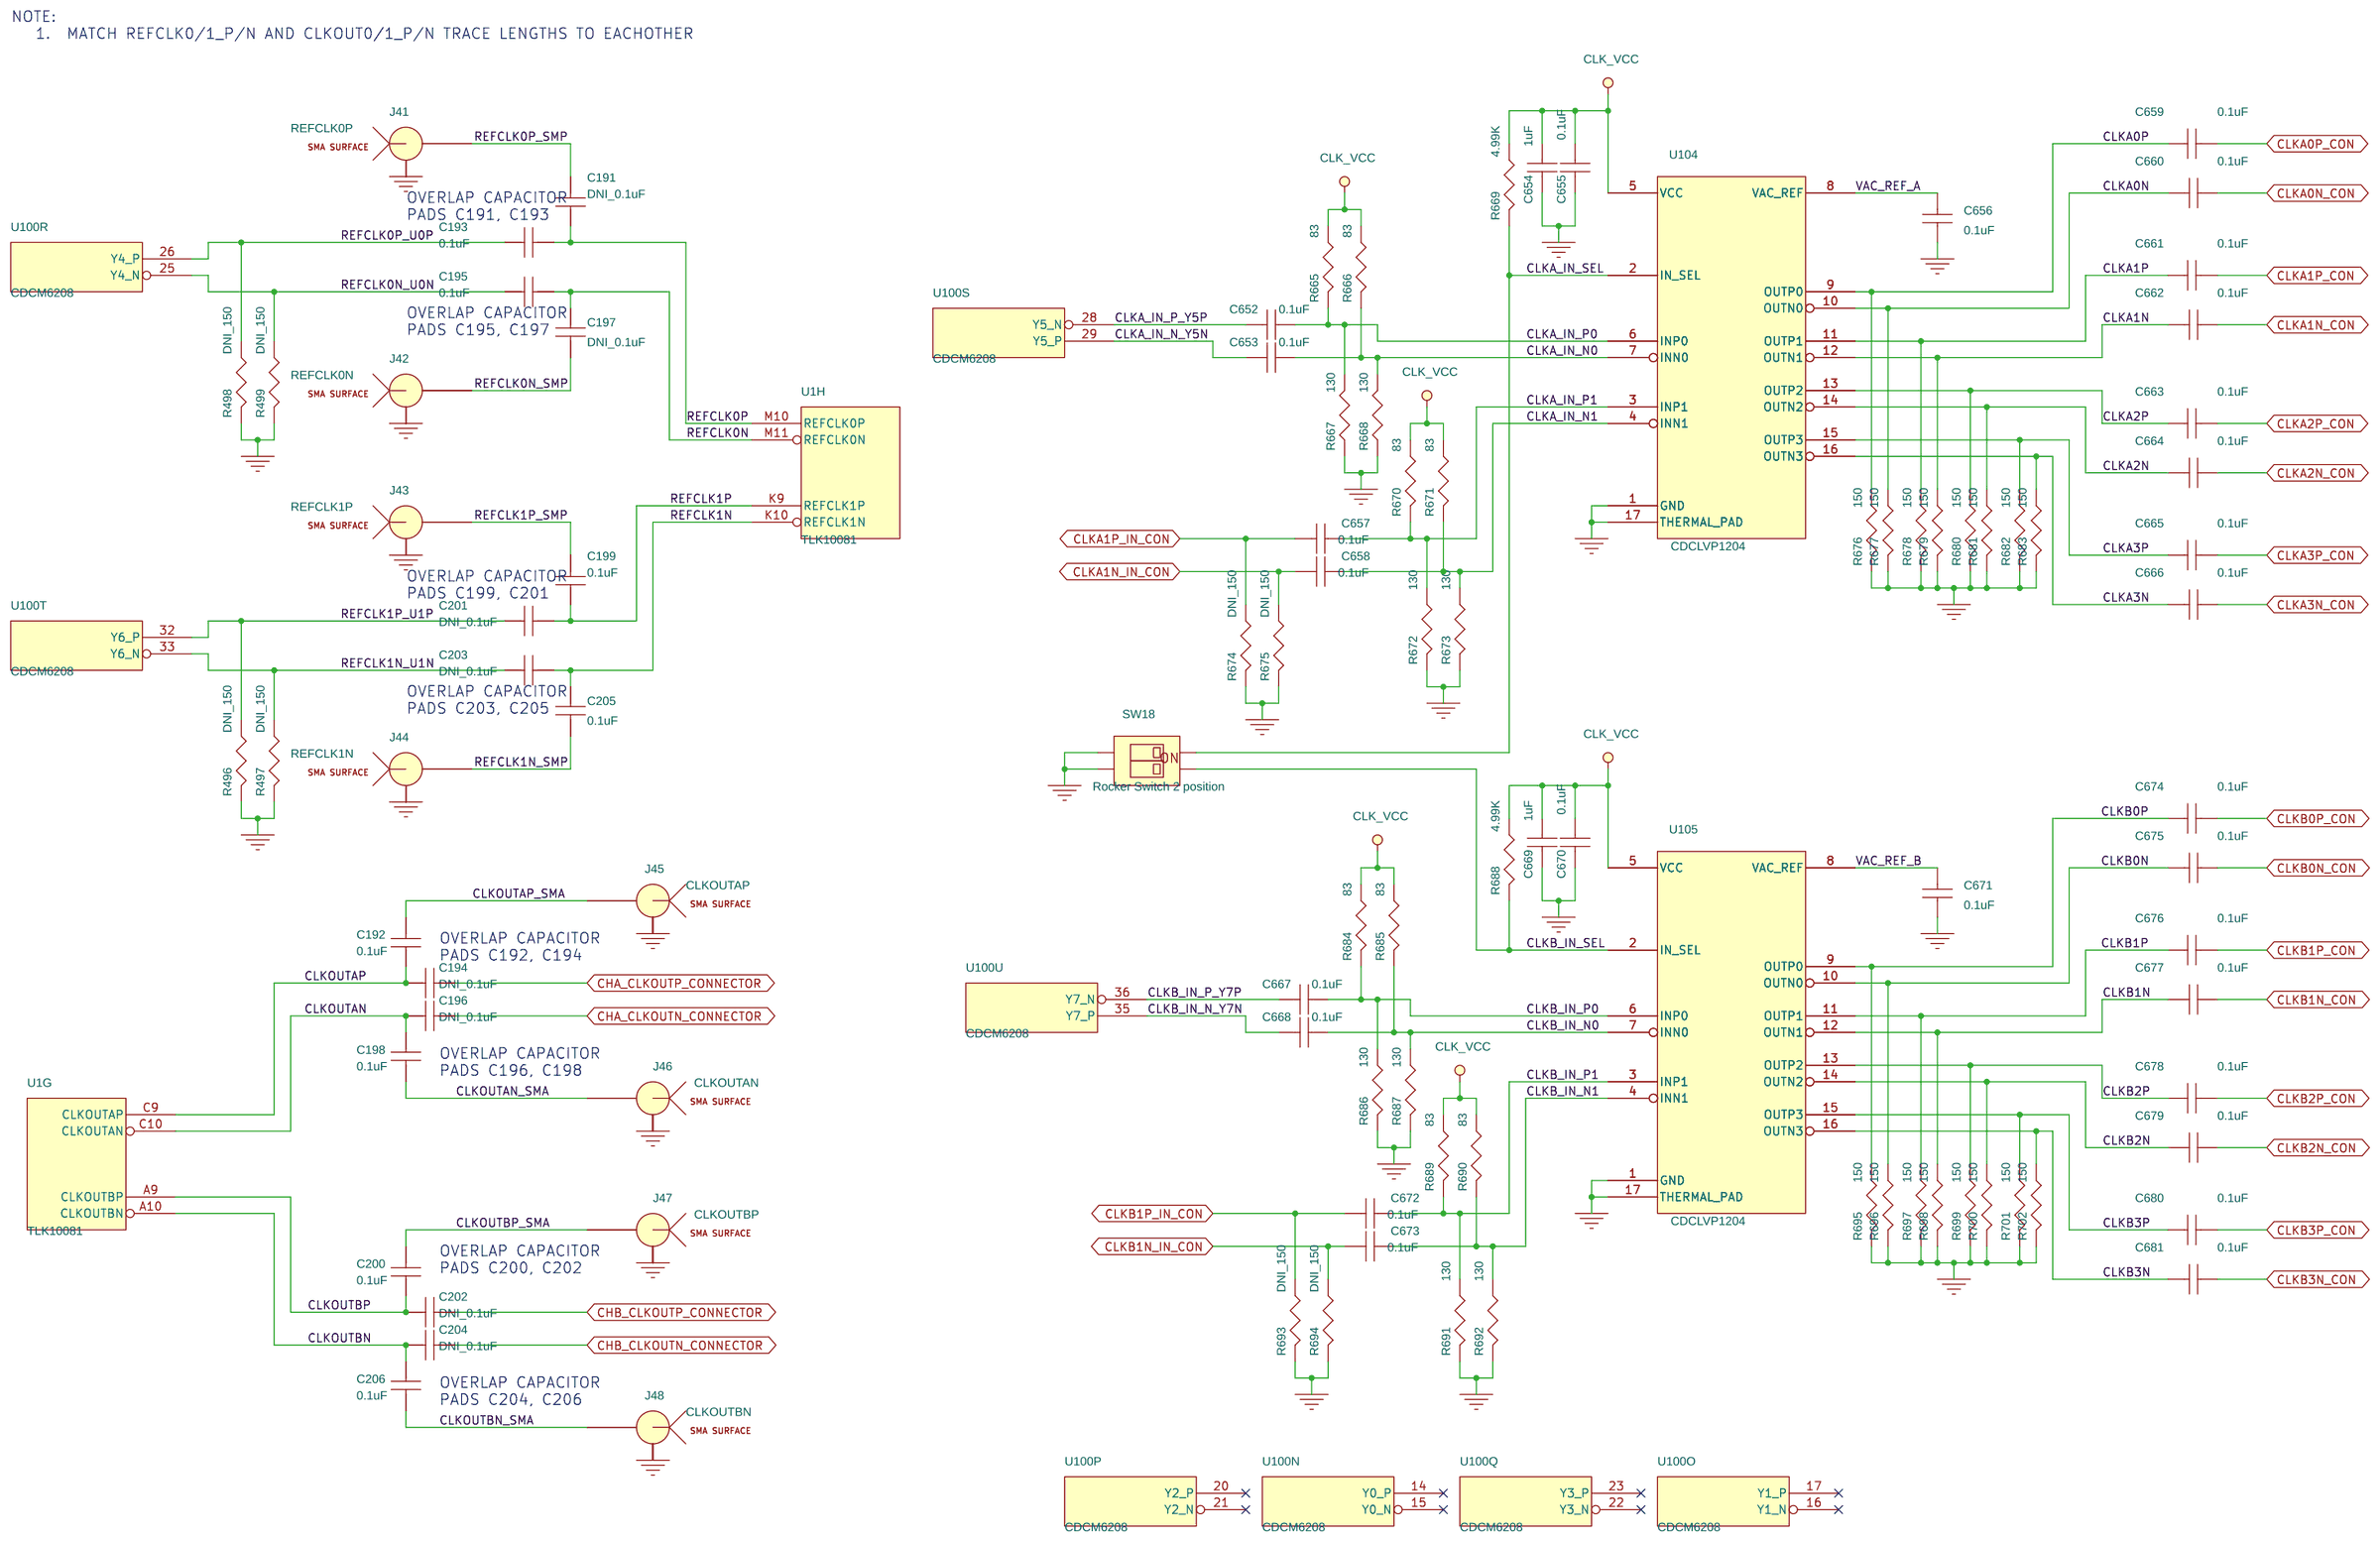
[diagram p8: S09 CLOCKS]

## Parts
sheet S02 1P0V REGULATORS
C15  100uF  [cc1812]
C16  4.7uF  [cc0603]
C17  68uF  [cc1210]
C18  10uF  [cc1206]
C19  1uF  [cc0603]
C20  1uF  [cc1206]
C21  0.001uF  [cc0603]
C22  100uF  [cc1812]
C23  4.7uF  [cc0603]
C24  68uF  [cc1210]
C25  10uF  [cc1206]
C26  1uF  [cc0603]
C27  1uF  [cc1206]
C28  0.001uF  [cc0603]
C600  100uF  [cc1812]
C601  4.7uF  [cc0603]
C602  1uF  [cc0603]
C603  0.001uF  [cc0603]
C604  68uF  [cc1210]
C605  10uF  [cc1206]
C606  1uF  [cc1206]
C607  100uF  [cc1812]
C608  4.7uF  [cc0603]
C609  1uF  [cc0603]
C610  0.001uF  [cc0603]
C611  68uF  [cc1210]
C612  10uF  [cc1206]
C613  1uF  [cc1206]
R49  4.99K  [r0603]
R50  1.13K  [r0603]
R52  4.02K  [r0603]
R66  4.99K  [r0603]
R67  1.13K  [r0603]
R69  4.02K  [r0603]
R600  88.7  [r0603]
R601  88.7  [r0603]
R602  4.99K  [r0603]
R603  1.13K  [r0603]
R604  4.02K  [r0603]
R605  88.7  [r0603]
R606  4.99K  [r0603]
R607  1.13K  [r0603]
R608  4.02K  [r0603]
R609  88.7  [r0603]
SW17  Rocker Switch 8 position  [gdh08s_thomasbetts]
TH1  Header 1x1  [Thermal_Hole]
TH2  Header 1x1  [Thermal_Hole]
TH3  Header 1x1  [Thermal_Hole]
TH4  Header 1x1  [Thermal_Hole]
TH5  Header 1x1  [Thermal_Hole]
TH6  Header 1x1  [Thermal_Hole]
TH7  Header 1x1  [Thermal_Hole]
TH8  Header 1x1  [Thermal_Hole]
U8  TPS74401RGW  [RGW20]
U10  TPS74401RGW  [RGW20]
U101  TPS74401RGW  [RGW20]
U102  TPS74401RGW  [RGW20]
sheet S03 1P5,1P8,2P5,3P3V REGULATORS
C29  100uF  [cc1812]
C30  4.7uF  [cc0603]
C31  1uF  [cc0603]
C32  68uF  [cc1210]
C33  10uF  [cc1206]
C34  1uF  [cc1206]
C35  0.015uF  [cc0603]
C43  100uF  [cc1812]
C44  4.7uF  [cc0603]
C45  1uF  [cc0603]
C46  68uF  [cc1210]
C47  10uF  [cc1206]
C48  1uF  [cc1206]
C49  0.015uF  [cc0603]
C64  100uF  [cc1812]
C65  4.7uF  [cc0603]
C66  1uF  [cc0603]
C67  68uF  [cc1210]
C68  10uF  [cc1206]
C69  1uF  [cc1206]
C70  10pF  [cc0603]
C71  100uF  [cc1812]
C72  4.7uF  [cc0603]
C73  1uF  [cc0603]
C74  68uF  [cc1210]
C75  10uF  [cc1206]
C76  1uF  [cc1206]
C77  10pF  [cc0603]
C614  1uF  [cc0402]
C615  1uF  [cc0201]
D100  GREEN  [LED_HSMB_C170DRA]
R83  4.99K  [r0603]
R84  4.12K  [r0603]
R86  4.53K  [r0603]
R117  4.99K  [r0603]
R118  3.57K  [r0603]
R120  2.8K  [r0603]
R168  4.99K  [r0603]
R169  3.57K  [r0603]
R171  1.13K  [r0603]
R185  4.99K  [r0603]
R186  3.57K  [r0603]
R188  1.13K  [r0603]
R610  3  [r0603]
R611  3  [r0603]
R612  47  [r0603]
R613  0  [r0603]
R614  4.99K  [r0402]
R615  DNI_4.99K  [r0402]
R616  250  [r0402]
TH9  Header 1x1  [Thermal_Hole]
TH10  Header 1x1  [Thermal_Hole]
TH11  Header 1x1  [Thermal_Hole]
TH12  Header 1x1  [Thermal_Hole]
TH13  Header 1x1  [Thermal_Hole]
TH14  Header 1x1  [Thermal_Hole]
TH15  Header 1x1  [Thermal_Hole]
TH16  Header 1x1  [Thermal_Hole]
U12  TPS74401RGW  [RGW20]
U16  TPS74401RGW  [RGW20]
U22  TPS74401RGW  [RGW20]
U24  TPS74401RGW  [RGW20]
U103  TLV70225  [SOT23_5pin]
sheet S04 POWER DISTRIBUTION
C80  10uF  [cc0805]
C84  10uF  [cc0805]
C85  1uF  [cc1206]
C86  0.1uF  [cc1206]
C87  0.01uF  [cc0805]
C89  1uF  [cc1206]
C90  0.1uF  [cc1206]
C91  0.01uF  [cc0805]
C93  10uF  [cc0805]
C94  1uF  [cc1206]
C95  0.1uF  [cc1206]
C97  10uF  [cc0805]
C98  0.01uF  [cc0805]
C99  1uF  [cc1206]
C100  0.1uF  [cc1206]
C101  0.01uF  [cc0805]
C107  10uF  [cc0805]
C108  10uF  [cc0805]
C109  1uF  [cc1206]
C110  0.1uF  [cc1206]
C111  0.01uF  [cc0805]
C113  1uF  [cc1206]
C114  0.1uF  [cc1206]
C115  0.01uF  [cc0805]
C117  10uF  [cc0805]
C118  10uF  [cc0805]
C119  1uF  [cc1206]
C120  0.1uF  [cc1206]
C121  0.01uF  [cc0805]
C123  1uF  [cc1206]
C124  0.1uF  [cc1206]
C125  0.01uF  [cc0805]
C127  10uF  [cc0805]
C128  1uF  [cc1206]
C129  0.1uF  [cc1206]
C130  0.01uF  [cc0805]
C136  68uF  [cc1210]
C137  10uF  [cc0805]
C138  1uF  [cc1206]
C139  0.1uF  [cc1206]
C140  0.01uF  [cc0805]
C616  10uF  [cc0805]
C617  0.1uF  [cc0402]
C618  10uF  [cc0805]
C619  0.1uF  [cc0402]
C620  10uF  [cc0805]
C621  0.1uF  [cc0402]
C622  10uF  [cc0805]
C623  0.1uF  [cc0402]
C624  10uF  [cc0805]
C625  0.1uF  [cc0402]
C626  10uF  [cc0805]
C627  0.1uF  [cc0402]
C628  10uF  [cc0805]
C629  0.1uF  [cc0402]
C630  10uF  [cc0805]
C631  1uF  [cc1206]
C632  0.1uF  [cc1206]
C633  0.01uF  [cc0805]
D9  BAT60A 10V, 3A  [SOD323]
JMP35  3 Pin Berg  [berg3]
JMP41  3 Pin Berg  [berg3]
L1  Ferrite Bead_1210  [r1210]
L2  Ferrite Bead_1210  [r1210]
L3  Ferrite Bead_1210  [r1210]
L4  Ferrite Bead_1210  [r1210]
L5  Ferrite Bead_1210  [r1210]
L6  Ferrite Bead_1210  [r1210]
L7  Ferrite Bead_1210  [r1210]
L8  Ferrite Bead_1210  [r1210]
L9  Ferrite Bead_1210  [r1210]
L14  Ferrite Bead_1210  [r1210]
L100  BLM15HD102SN1D  [0603]
L101  BLM15HD102SN1D  [0603]
L102  BLM15HD102SN1D  [0603]
L103  BLM15HD102SN1D  [0603]
L104  BLM15HD102SN1D  [0603]
L105  BLM15HD102SN1D  [0603]
L106  BLM15HD102SN1D  [0603]
P1  5V_BJ  [bjack]
P14  GND  [bjack]
P26  RAPC722  [con_rapc722_jack_thvt_3]
sheet S06 DEVICE POWER GROUND
C141  0.1uF  [cc0402]
C142  0.1uF  [cc0402]
C143  0.1uF  [cc0402]
C144  0.1uF  [cc0402]
C145  0.1uF  [cc0402]
C146  0.1uF  [cc0402]
C147  0.1uF  [cc0402]
C148  0.1uF  [cc0402]
C149  0.1uF  [cc0402]
C150  0.1uF  [cc0402]
C151  0.1uF  [cc0402]
C152  0.1uF  [cc0402]
C153  0.1uF  [cc0402]
C163  0.1uF  [cc0402]
C164  0.1uF  [cc0402]
C165  0.1uF  [cc0402]
C166  0.1uF  [cc0402]
C167  0.1uF  [cc0402]
C168  0.1uF  [cc0402]
C169  0.1uF  [cc0402]
C170  0.1uF  [cc0402]
C171  0.1uF  [cc0402]
C172  0.1uF  [cc0402]
C173  0.1uF  [cc0402]
C174  0.1uF  [cc0402]
C188  0.1uF  [cc0402]
C638  0.1uF  [cc0402]
C639  0.1uF  [cc0402]
C640  0.1uF  [cc0402]
C641  0.1uF  [cc0402]
C642  0.1uF  [cc0402]
C643  0.1uF  [cc0402]
C644  0.1uF  [cc0402]
C645  0.1uF  [cc0402]
C646  0.1uF  [cc0402]
C647  0.1uF  [cc0402]
C648  0.1uF  [cc0402]
C649  0.1uF  [cc0402]
C650  0.1uF  [cc0402]
C651  0.1uF  [cc0402]
sheet S07 GLOBAL SIGNALS
C189  0.1uF  [cc0402]
C190  1uF  [cc0402]
C274  1uF  [cc0402]
C275  1uF  [cc0402]
C278  1uF  [cc0402]
C279  1uF  [cc0402]
C282  1uF  [cc0402]
C283  1uF  [cc0402]
D10  RED  [LED_HSMB_C170DRA]
D11  GREEN  [LED_HSMB_C170DRA]
D12  RED  [LED_HSMB_C170DRA]
D13  RED  [LED_HSMB_C170DRA]
D14  GREEN  [LED_HSMB_C170DRA]
D15  GREEN  [LED_HSMB_C170DRA]
D16  GREEN  [LED_HSMB_C170DRA]
JMP42  3 Pin Berg  [berg3]
JMP48  Header 5x2  [berg2x5]
JMP61  Header 4x2  [berg2x4]
JMP100  2 Pin Berg  [berg2]
Q3  FDV301N  [SOT23]
Q4  FDV301N  [SOT23]
Q5  FDV301N  [SOT23]
Q6  FDV301N  [SOT23]
Q7  FDV301N  [SOT23]
Q100  FDV301N  [SOT23]
R239  4.99K  [r0603]
R240  DNI_4.99K  [r0402]
R241  4.99K  [r0603]
R242  130  [r0603]
R243  49.9  [r0603]
R244  100K  [r0603]
R245  4.99K  [r0402]
R246  130  [r0603]
R247  49.9K  [r0402]
R248  49.9K  [r0402]
R249  49.9K  [r0402]
R250  49.9K  [r0402]
R251  49.9K  [r0402]
R252  49.9K  [r0402]
R253  49.9K  [r0402]
R254  49.9K  [r0402]
R255  49.9K  [r0402]
R256  DNI_4.99K  [r0402]
R257  DNI_4.99K  [r0402]
R258  20K  [r0402]
R259  20K  [r0402]
R262  DNI_4.99K  [r0402]
R263  DNI_4.99K  [r0402]
R273  0  [r0402]
R274  0  [r0402]
R275  0  [r0402]
R276  0  [r0402]
R277  0  [r0402]
R278  250  [r0402]
R279  0  [r0402]
R280  250  [r0402]
R281  250  [r0402]
R282  250  [r0402]
R283  0  [r0402]
R284  250  [r0402]
R285  0  [r0402]
R286  0  [r0402]
R287  0  [r0402]
R459  0  [r0402]
R460  0  [r0402]
R461  0  [r0402]
R462  0  [r0402]
R463  0  [r0402]
R465  49.9K  [r0603]
R466  0  [r0402]
R486  0  [r0402]
R532  0  [r0402]
R533  0  [r0402]
R617  DNI_4.99K  [r0402]
R618  DNI_4.99K  [r0402]
R619  49.9K  [r0402]
R620  49.9K  [r0402]
R621  0  [r0402]
R622  0  [r0402]
R623  DNI_0  [r0402]
R624  DNI_0  [r0402]
R625  DNI_4.99K  [r0402]
R626  DNI_4.99K  [r0402]
R627  DNI_4.99K  [r0402]
R628  DNI_4.99K  [r0402]
R629  0  [r0402]
R630  0  [r0402]
R631  4.99K  [r0402]
R632  0  [r0402]
R633  0  [r0402]
SW10  B3U-1100P  [OMRON_3PIN_US_B3U-1100P]
SW11  Rocker Switch 10 position  [gdh10s_thomasbetts]
U36  SN74AVCH1T45DBV  [DCK6]
U37  TPS3125J18  [SOT23_5pin]
U38  ZXTD09N50DE6  [DDC6]
U41  TXB0108PWR  [PW20]
U64  TXB0108PWR  [PW20]
sheet S08 MDIO, JTAG, I2C INTERFACE
C280  1uF  [cc0402]
C281  1uF  [cc0402]
C286  1uF  [cc0402]
C302  1uF  [cc0402]
C303  1uF  [cc0402]
C304  1uF  [cc0402]
J101  MEC1-120-02-F-D-A Connector  [MEC1-120-02-F-D-A]  (sections A,B)
JMP47  Header 5x2  [berg2x5]
JMP50  Header 2x2  [berg2X2]
JMP62  3 Pin Berg  [berg3]
JMP77  Header T 4pin  [berg2X3tee]
JMP101  Header 2x1  [HDR_THVT_1X2_100]
JMP102  Header 2x6  [HDR_THVT_2X6_100]
JMP103  Header 2x2  [HDR_THVT_2X2_100]
K1  AQY221R2T  [Panasonic_AQY221R2T_VSSOP]
K2  AQY221R2T  [Panasonic_AQY221R2T_VSSOP]
K3  AQY221R2T  [Panasonic_AQY221R2T_VSSOP]
K4  AQY221R2T  [Panasonic_AQY221R2T_VSSOP]
Q101  FDV301N  [FAIRCHILD_NFET_FDV301N]
Q102  FDV301N  [FAIRCHILD_NFET_FDV301N]
Q103  FDV301N  [FAIRCHILD_NFET_FDV301N]
Q104  FDV301N  [FAIRCHILD_NFET_FDV301N]
R268  DNI_0  [r0603]
R269  0  [r0603]
R270  4.99K  [r0402]
R288  4.02K  [r0402]
R289  4.02K  [r0402]
R290  DNI_4.02K  [r0402]
R291  DNI_4.02K  [r0402]
R292  0  [r0201]
R293  DNI_0  [r0402]
R294  0  [r0201]
R295  DNI_0  [r0402]
R296  0  [r0402]
R297  0  [r0402]
R298  DNI_0  [r0402]
R299  DNI_0  [r0402]
R300  4.99K  [r0402]
R301  4.99K  [r0402]
R302  4.99K  [r0402]
R303  4.99K  [r0402]
R304  4.99K  [r0402]
R305  4.99K  [r0402]
R306  4.02K  [r0402]
R307  4.02K  [r0402]
R308  0  [r0402]
R309  0  [r0402]
R451  0  [r0201]
R472  DNI_4.99K  [r0402]
R473  DNI_4.99K  [r0402]
R476  DNI_2K  [r0402]
R477  DNI_2K  [r0402]
R491  0  [r0201]
R508  0  [r0402]
R509  0  [r0402]
R510  0  [r0402]
R511  0  [r0402]
R634  DNI_0  [r0402]
R635  DNI_0  [r0402]
R636  DNI_0  [r0402]
R637  DNI_0  [r0402]
R638  DNI_4.99K  [0402]
R639  DNI_0  [0603]
R640  DNI_0  [0603]
R641  100  [0402]
R642  4.99K  [0402]
R643  49.9K  [0402]
R644  100  [0402]
R645  4.99K  [0402]
R646  49.9K  [0402]
R647  DNI_4.99K  [0402]
R648  4.99K  [0402]
R649  DNI_0  [r0402]
R650  DNI_0  [r0402]
R651  0  [0402]
R652  0  [0402]
R653  0  [0402]
R654  0  [0402]
R655  0  [0402]
R656  0  [0402]
R657  DNI_4.99K  [0402]
R658  DNI_4.99K  [0402]
R659  0  [0402]
R660  0  [0402]
R661  0  [0402]
R662  0  [0402]
R663  0  [0402]
R664  0  [0402]
SW12  Rocker Switch 4 position  [gdh04s_thomasbetts]
U1  TLK10081  [ZWQ144]  (sections A,B,C,D,E,F,G,H,I,J,K,L,M,N,O,P,Q,R,S,T,U)
U40  TXB0108PWR  [PW20]
U42  TCA6424  [rgj32]  (sections A,B,C,D)
U43  TXS0108EPWR  [PW20]
sheet S09 CLOCKS
C191  DNI_0.1uF  [cc0201]
C192  0.1uF  [cc0201]
C193  0.1uF  [cc0201]
C194  DNI_0.1uF  [cc0201]
C195  0.1uF  [cc0201]
C196  DNI_0.1uF  [cc0201]
C197  DNI_0.1uF  [cc0201]
C198  0.1uF  [cc0201]
C199  0.1uF  [cc0201]
C200  0.1uF  [cc0201]
C201  DNI_0.1uF  [cc0201]
C202  DNI_0.1uF  [cc0201]
C203  DNI_0.1uF  [cc0201]
C204  DNI_0.1uF  [cc0201]
C205  0.1uF  [cc0201]
C206  0.1uF  [cc0201]
C652  0.1uF  [cc0201]
C653  0.1uF  [cc0201]
C654  1uF  [cc0402]
C655  0.1uF  [cc0402]
C656  0.1uF  [cc0402]
C657  0.1uF  [cc0201]
C658  0.1uF  [cc0201]
C659  0.1uF  [cc0201]
C660  0.1uF  [cc0201]
C661  0.1uF  [cc0201]
C662  0.1uF  [cc0201]
C663  0.1uF  [cc0201]
C664  0.1uF  [cc0201]
C665  0.1uF  [cc0201]
C666  0.1uF  [cc0201]
C667  0.1uF  [cc0201]
C668  0.1uF  [cc0201]
C669  1uF  [cc0402]
C670  0.1uF  [cc0402]
C671  0.1uF  [cc0402]
C672  0.1uF  [cc0201]
C673  0.1uF  [cc0201]
C674  0.1uF  [cc0201]
C675  0.1uF  [cc0201]
C676  0.1uF  [cc0201]
C677  0.1uF  [cc0201]
C678  0.1uF  [cc0201]
C679  0.1uF  [cc0201]
C680  0.1uF  [cc0201]
C681  0.1uF  [cc0201]
J41  REFCLK0P  [32k141-40m-fr4wvia]
J42  REFCLK0N  [32k141-40m-fr4wvia]
J43  REFCLK1P  [32k141-40m-fr4wvia]
J44  REFCLK1N  [32k141-40m-fr4wvia]
J45  CLKOUTAP  [32k141-40m-fr4wvia]
J46  CLKOUTAN  [32k141-40m-fr4wvia]
J47  CLKOUTBP  [32k141-40m-fr4wvia]
J48  CLKOUTBN  [32k141-40m-fr4wvia]
R496  DNI_150  [r0201]
R497  DNI_150  [r0201]
R498  DNI_150  [r0201]
R499  DNI_150  [r0201]
R665  83  [r0201]
R666  83  [r0201]
R667  130  [r0201]
R668  130  [r0201]
R669  4.99K  [0402]
R670  83  [r0201]
R671  83  [r0201]
R672  130  [r0201]
R673  130  [r0201]
R674  DNI_150  [r0201]
R675  DNI_150  [r0201]
R676  150  [r0201]
R677  150  [r0201]
R678  150  [r0201]
R679  150  [r0201]
R680  150  [r0201]
R681  150  [r0201]
R682  150  [r0201]
R683  150  [r0201]
R684  83  [r0201]
R685  83  [r0201]
R686  130  [r0201]
R687  130  [r0201]
R688  4.99K  [0402]
R689  83  [r0201]
R690  83  [r0201]
R691  130  [r0201]
R692  130  [r0201]
R693  DNI_150  [r0201]
R694  DNI_150  [r0201]
R695  150  [r0201]
R696  150  [r0201]
R697  150  [r0201]
R698  150  [r0201]
R699  150  [r0201]
R700  150  [r0201]
R701  150  [r0201]
R702  150  [r0201]
SW18  Rocker Switch 2 position  [gdh02s_thomasbetts]
U104  CDCLVP1204  [QFN50P300X300X100-16]
U105  CDCLVP1204  [QFN50P300X300X100-16]
sheet S11 CRYSTAL OSCILLATORS
U100  CDCM6208  [hqfn_48_282x282_20]  (sections A,B,C,D,E,F,G,H,I,J,K,L,M,N,O,P,Q,R,S,T,U,V,W,X)
sheet S15 BOARD TO BOARD CLOCK
J102  SEAF_ASP-134486-01  [ASP-134486]  (sections A,B,C,D,E,F,G,H,I,J,K)

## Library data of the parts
C15 C16 C19 C21-C23 C26 C28-C31 C35 C43-C45 C49 C64-C66 C70-C73 C77 C189 C190 C274 C275 C278-C283 C286 C302-C304 C600-C603 C607-C610 = CAP_NP
C17 C18 C20 C24 C25 C27 C32-C34 C46-C48 C67-C69 C74-C76 C85 C89 C94 C99 C109 C113 C119 C123 C128 C136 C138 C604-C606 C611-C613 C631 = NPCap1206_1.0uf
R49 R50 R52 R66 R67 R69 R83 R84 R86 R117 R118 R120 R168 R169 R171 R185 R186 R188 R239 R241-R244 R246 R268 R269 R288-R295 R305-R307 R465 R600-R613 R621-R635 R638 R641 R644 R647 R648 R669 R688 = r0603
SW17 = Rocker_Switch_8_position_1
TH1-TH16 = Header_1x1_0
U8 U10 U12 U16 U22 U24 U101 U102 = TPS74x01RGW_0
C141-C153 C163-C174 C188 C191-C206 C614 C615 C617 C619 C621 C623 C625 C627 C629 C638-C681 = cc0402
D11 D16 D100 = LED_HSMG: Mfr_Part_Number: HSMG-C170
R240 R245 R247-R259 R262 R263 R270 R273-R287 R300-R304 R459-R463 R466 R472 R473 R476 R477 R486 R496-R499 R508-R511 R532 R533 R614-R620 R642 R643 R645 R646 R649-R668 R670-R687 R689-R702 = r0402
U103 = TLV713
C80 C84 C93 C97 C107 C108 C117 C118 C127 C137 C616 C618 C620 C622 C624 C626 C628 C630 = CAP_NP: Vendor: Digi-Key
C86 C90 C95 C100 C110 C114 C120 C124 C129 C139 C632 = NPCap1206_0.1uf
C87 C91 C98 C101 C111 C115 C121 C125 C130 C140 C633 = NPCap0805_0.01uf
D9 = BAT60A
JMP35 JMP41 JMP42 = 3_Pin_Berg_Jumper
L1-L9 L14 = Ferrite_Bead_1206
L100-L106 = INDUCTOR_0: 2nd-Alt-P/N: N/A; 5th Part Field: 46-000-001
P1 P14 = Banana-Jack
P26 = RAPC722: SILK: +5V
D10 D12 = LED_HSMS: Mfr_Part_Number: HSMS-C170
D13 = LED_HSMS
D14 D15 = LED_HSMG
JMP47 JMP48 = Header_5x2
JMP61 = Header_4x2
JMP100 = 2_Pin_Berg_Jumper
Q3-Q7 Q100-Q104 = FDV301N_NFET_1
SW10 = B3U-1100P
SW11 = Rocker_Switch_10_position_0
U36 = SN74AVCH1T45DBV: PART_NUMBER: SN74AVCH1T45DCK
U37 = TPS3125J18_0
U38 = ZXTD09N50DE6
U40 U41 U64 = TXB0108PWR
J101 = MEC1-120-02-F-D-A_Connector
JMP50 JMP103 = Header_2x2
JMP62 = 3_Pin_Berg_Jumper_Single_Side
JMP77 = Header_T_4pin
JMP101 = 2_Pin_Berg_Jumper_Straight
JMP102 = Header_6x2
K1-K4 = AQY221R2T
R296-R299 R308 R309 R451 R491 R636 R637 R639 R640 = r0201
SW12 = Rocker_Switch_4_position_0
U1 = TLK10081
U42 = TCA6424_0
U43 = TXS0108EPWR
J41-J48 = sma_surface
SW18 = Rocker_Switch_2_position
U104 U105 = CDCLVP1204
U100 = CDCM6208
J102 = SEAF_ASP-134486-01_0

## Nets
1P5/8V: JMP35.2 L2.1 L4.1 L6.1 L8.1 L9.1
5V: C15.1 C16.1 C19.1 C22.1 C23.1 C26.1 C29.1 C30.1 C31.1 C43.1 C44.1 C45.1 C64.1 C65.1 C66.1 C71.1 C72.1 C73.1 C136.1 C137.1 C138.1 C139.1 C140.1 C600.1 C601.1 C602.1 C607.1 C608.1 C609.1 C614.1 L14.2 R49.1 R66.1 R83.1 R117.1 R168.1 R185.1 R242.1 R246.1 R278.1 R280.1 R281.1 R282.1 R284.1 R602.1 R606.1 R640.2 U8.5(IN1) U8.6(IN2) U8.7(IN3) U8.8(IN4) U8.10(BIAS) U10.5(IN1) U10.6(IN2) U10.7(IN3) U10.8(IN4) U10.10(BIAS) U12.5(IN1) U12.6(IN2) U12.7(IN3) U12.8(IN4) U12.10(BIAS) U16.5(IN1) U16.6(IN2) U16.7(IN3) U16.8(IN4) U16.10(BIAS) U22.5(IN1) U22.6(IN2) U22.7(IN3) U22.8(IN4) U22.10(BIAS) U24.5(IN1) U24.6(IN2) U24.7(IN3) U24.8(IN4) U24.10(BIAS) U101.5(IN1) U101.6(IN2) U101.7(IN3) U101.8(IN4) U101.10(BIAS) U102.5(IN1) U102.6(IN2) U102.7(IN3) U102.8(IN4) U102.10(BIAS) U103.1(IN) ; also on sheet 10 13 14
5V_BARREL: D9.2(A) P26.3(TIP)
5V_BJ: JMP41.1 P1.1(V)
5V_DIODE: D9.1(C) JMP41.3
5V_SOURCE: JMP41.2 L14.1
5V_USB: J101.1 R640.1
DVDD: C117.1 C119.1 C120.1 C121.1 C170.1 C171.1 C172.1 C173.1 C174.1 L7.2 U1.D7(1P0V_VPP) U1.E7(1P0V_DVDD1) U1.F7(1P0V_DVDD2) U1.G6(1P0V_DVDD3) U1.G8(1P0V_DVDD4) U1.H7(1P0V_DVDD5) ; also on sheet 14
GND: C15.2 C16.2 C17.2 C18.2 C19.2 C20.2 C21.2 C22.2 C23.2 C24.2 C25.2 C26.2 C27.2 C28.2 C29.2 C30.2 C31.2 C32.2 C33.2 C34.2 C35.2 C43.2 C44.2 C45.2 C46.2 C47.2 C48.2 C49.2 C64.2 C65.2 C66.2 C67.2 C68.2 C69.2 C70.2 C71.2 C72.2 C73.2 C74.2 C75.2 C76.2 C77.2 C80.2 C84.2 C85.2 C86.2 C87.2 C89.2 C90.2 C91.2 C93.2 C94.2 C95.2 C97.2 C98.2 C99.2 C100.2 C101.2 C107.2 C108.2 C109.2 C110.2 C111.2 C113.2 C114.2 C115.2 C117.2 C118.2 C119.2 C120.2 C121.2 C123.2 C124.2 C125.2 C127.2 C128.2 C129.2 C130.2 C136.2 C137.2 C138.2 C139.2 C140.2 C141.2 C142.2 C143.2 C144.2 C145.2 C146.2 C147.2 C148.2 C149.2 C150.2 C151.2 C152.2 C153.2 C163.2 C164.2 C165.2 C166.2 C167.2 C168.2 C169.2 C170.2 C171.2 C172.2 C173.2 C174.2 C188.2 C189.2 C190.2 C274.2 C275.2 C278.2 C279.2 C280.2 C281.2 C282.2 C283.2 C286.2 C302.2 C303.2 C304.2 C600.2 C601.2 C602.2 C603.2 C604.2 C605.2 C606.2 C607.2 C608.2 C609.2 C610.2 C611.2 C612.2 C613.2 C614.2 C615.2 C616.2 C617.2 C618.2 C619.2 C620.2 C621.2 C622.2 C623.2 C624.2 C625.2 C626.2 C627.2 C628.2 C629.2 C630.2 C631.2 C632.2 C633.2 C638.2 C639.2 C640.2 C641.2 C642.2 C643.2 C644.2 C645.2 C646.2 C647.2 C648.2 C649.2 C650.2 C651.2 C654.2 C655.2 C656.1 C669.2 C670.2 C671.1 D100.1 J41.2 J41.3 J41.4 J41.5 J42.2 J42.3 J42.4 J42.5 J43.2 J43.3 J43.4 J43.5 J44.2 J44.3 J44.4 J44.5 J45.2 J45.3 J45.4 J45.5 J46.2 J46.3 J46.4 J46.5 J47.2 J47.3 J47.4 J47.5 J48.2 J48.3 J48.4 J48.5 J101.3 J101.4 J101.5 J101.6 J102.A1 J102.A4 J102.A5 J102.A8 J102.A9 J102.A12 J102.A13 J102.A16 J102.A17 J102.A20 J102.A21 J102.A24 J102.A25 J102.A28 J102.A29 J102.A32 J102.A33 J102.A36 J102.A38 J102.A40 J102.B1 J102.B2 J102.B3 J102.B4 J102.B5 J102.B6 J102.B7 J102.B8 J102.B9 J102.B10 J102.B11 J102.B12 J102.B13 J102.B14 J102.B15 J102.B16 J102.B17 J102.B18 J102.B19 J102.B20 J102.B21 J102.B22 J102.B23 J102.B24 J102.B25 J102.B26 J102.B27 J102.B28 J102.B29 J102.B30 J102.B31 J102.B32 J102.B33 J102.B34 J102.B35 J102.B36 J102.B37 J102.B38 J102.B39 J102.B40 J102.C2 J102.C4 J102.D1 J102.D2 J102.D3 J102.D4 J102.E2 J102.E4 J102.F1 J102.F2 J102.F3 J102.F4 J102.G2 J102.G4 J102.H1 J102.H2 J102.H3 J102.H4 J102.J1 J102.J2 J102.J3 J102.J4 J102.J5 J102.J6 J102.J7 J102.J8 J102.J9 J102.J10 J102.J11 J102.J12 J102.J13 J102.J14 J102.J15 J102.J16 J102.J17 J102.J18 J102.J19 J102.J20 J102.J21 J102.J22 J102.J23 J102.J24 J102.J25 J102.J26 J102.J27 J102.J28 J102.J29 J102.J30 J102.J31 J102.J32 J102.J33 J102.J34 J102.J35 J102.J36 J102.J37 J102.J38 J102.J39 J102.J40 J102.K1 J102.K4 J102.K5 J102.K8 J102.K9 J102.K12 J102.K13 J102.K16 J102.K17 J102.K20 J102.K21 J102.K24 J102.K25 J102.K28 J102.K29 J102.K32 J102.K33 J102.K36 J102.K38 J102.K40 JMP42.3 JMP47.2 JMP47.4 JMP47.6 JMP47.8 JMP47.10 JMP48.2 JMP48.4 JMP48.6 JMP48.8 JMP48.10 JMP50.1 JMP50.3 JMP61.1 JMP61.2 JMP61.7 JMP61.8 JMP62.3 JMP77.4 JMP100.2 JMP101.2 JMP102.2 JMP102.4 JMP102.6 JMP102.8 JMP102.10 JMP102.12 JMP103.2 JMP103.4 K1.2(GND) K2.2(GND) K3.2(GND) K4.2(GND) P14.1(V) P26.1(SLEEVE) Q3.2(S) Q4.2(S) Q5.2(S) Q6.2(S) Q7.2(S) Q100.2(S) Q101.2(S) Q102.2(S) Q103.2(S) Q104.2(S) R245.1 R262.2 R263.2 R496.2 R497.2 R498.2 R499.2 R600.1 R601.1 R605.1 R609.1 R610.1 R611.1 R612.1 R613.1 R615.1 R617.2 R618.2 R619.2 R620.2 R627.2 R628.2 R638.1 R647.1 R667.1 R668.1 R672.2 R673.2 R674.2 R675.2 R676.2 R677.2 R678.2 R679.2 R680.2 R681.2 R682.2 R683.2 R686.2 R687.2 R691.2 R692.2 R693.2 R694.2 R695.2 R696.2 R697.2 R698.2 R699.2 R700.2 R701.2 R702.2 SW10.2 SW10.3(CASE) SW11.2 SW11.4 SW11.6 SW11.8 SW11.10 SW11.12 SW11.14 SW11.16 SW11.18 SW11.20 SW12.2 SW12.4 SW12.6 SW12.8 SW17.2 SW17.4 SW17.6 SW17.8 SW17.10 SW17.12 SW17.14 SW17.16 SW18.2 SW18.4 TH1.1 TH2.1 TH3.1 TH4.1 TH5.1 TH6.1 TH7.1 TH8.1 TH9.1 TH10.1 TH11.1 TH12.1 TH13.1 TH14.1 TH15.1 TH16.1 U1.A2(VSS1) U1.A5(VSS2) U1.A11(VSS3) U1.B3(VSS4) U1.B4(VSS5) U1.B7(VSS6) U1.B11(VSS7) U1.C1(VSS8) U1.C6(VSS9) U1.C12(VSS10) U1.D3(VSS11) U1.D5(VSS12) U1.D10(VSS13) U1.D11(VSS14) U1.E2(VSS15) U1.E4(VSS16) U1.F1(VSS17) U1.F5(VSS18) U1.F8(VSS19) U1.F10(VSS20) U1.F12(VSS21) U1.G1(VSS22) U1.G3(VSS23) U1.G5(VSS24) U1.G7(VSS25) U1.G11(VSS26) U1.H2(VSS27) U1.H4(VSS28) U1.H11(VSS29) U1.J5(VSS30) U1.J12(VSS31) U1.K1(VSS32) U1.K6(VSS33) U1.K11(VSS34) U1.L3(VSS35) U1.L4(VSS36) U1.L7(VSS37) U1.L11(VSS38) U1.M2(VSS39) U1.M5(VSS40) U1.M12(VSS41) U8.12(GND) U8.21(GND_PP) U10.12(GND) U10.21(GND_PP) U12.12(GND) U12.21(GND_PP) U16.12(GND) U16.21(GND_PP) U22.12(GND) U22.21(GND_PP) U24.12(GND) U24.21(GND_PP) U36.2(GND) U37.2(GND) U38.2(E1) U38.5(E2) U40.11(GND) U41.11(GND) U42.25(GND) U42.33(PP) U43.11(GND) U64.11(GND) U100.49(GND) U101.12(GND) U101.21(GND_PP) U102.12(GND) U102.21(GND_PP) U103.2(GND) U104.1(GND) U104.17(THERMAL_PAD) U105.1(GND) U105.17(THERMAL_PAD) ; also on sheet 10 12 13 14 15
VDDA: C80.1 C85.1 C86.1 C87.1 C141.1 C142.1 C143.1 C144.1 C145.1 C146.1 L1.2 R256.2 R257.2 U1.D2(1P0V_VDDA_LS_HS1) U1.F2(1P0V_VDDA_LS_HS2) U1.F11(1P0V_VDDA_LS_HS5) U1.G2(1P0V_VDDA_LS_HS3) U1.G10(1P0V_VDDA_LS_HS6) U1.J2(1P0V_VDDA_LS_HS4) ; also on sheet 14
VDDD: C107.1 C109.1 C110.1 C111.1 C164.1 C165.1 C166.1 C167.1 C168.1 L5.2 U1.E6(1P0V_VDDD1) U1.E8(1P0V_VDDD2) U1.F6(1P0V_VDDD3) U1.H6(1P0V_VDDD4) U1.H8(1P0V_VDDD5) ; also on sheet 14
VDDO: C127.1 C128.1 C129.1 C130.1 C147.1 C148.1 C149.1 C274.1 C279.1 C282.1 C286.1 C304.1 L9.2 R239.1 R240.2 R247.1 R248.1 R249.1 R250.1 R251.1 R252.1 R253.1 R254.1 R255.1 R268.1 R270.1 R288.1 R289.2 R300.1 R301.1 R302.1 R303.1 R304.1 R305.2 R625.1 R626.1 R631.1 U1.C7(1P5_8V_VDDO0) U1.K7(1P5_8V_VDDO1) U36.1(VCCA) U40.2(VCCA) U41.2(VCCA) U43.2(VCCA) U64.2(VCCA) ; also on sheet 14
VDDRA_HS: C97.1 C99.1 C100.1 C101.1 C163.1 L4.2 U1.E11(1P5_8V_VDDRA_HS) ; also on sheet 14
VDDRA_LS: C84.1 C89.1 C90.1 C91.1 C150.1 L2.2 U1.C3(1P5_8V_VDDRA_LS) ; also on sheet 14
VDDRB_HS: C118.1 C123.1 C124.1 C125.1 C188.1 L8.2 U1.J11(1P5_8V_VDDRB_HS) ; also on sheet 14
VDDRB_LS: C108.1 C113.1 C114.1 C115.1 C169.1 L6.2 U1.K3(1P5_8V_VDDRB_LS) ; also on sheet 14
VDDT: C93.1 C94.1 C95.1 C98.1 C151.1 C152.1 C153.1 L3.2 U1.F4(1P0V_VDDT_LS_HS1) U1.F9(1P0V_VDDT_LS_HS3) U1.G4(1P0V_VDDT_LS_HS2) ; also on sheet 14
1P0V_A1: C17.1 C18.1 C20.1 L1.1 R50.1 U8.1(OUT1) U8.18(OUT2) U8.19(OUT3) U8.20(OUT4) ; also on sheet 14
1P0V_A1_REG_ADJ: R50.2 R52.2 U8.16(FB)
1P0V_A1_REG_EN: R49.2 SW17.1 U8.11(EN)
1P0V_A1_REG_SS: C21.1 U8.15(SS)
1P0V_A1_REG_TRIM: R52.1 R600.2
1P0V_A2: C604.1 C605.1 C606.1 L3.1 R603.1 U101.1(OUT1) U101.18(OUT2) U101.19(OUT3) U101.20(OUT4) ; also on sheet 14
1P0V_A2_REG_ADJ: R603.2 R604.2 U101.16(FB)
1P0V_A2_REG_EN: R602.2 SW17.3 U101.11(EN)
1P0V_A2_REG_SS: C603.1 U101.15(SS)
1P0V_A2_REG_TRIM: R604.1 R605.2
1P0V_D1: C24.1 C25.1 C27.1 L5.1 R67.1 U10.1(OUT1) U10.18(OUT2) U10.19(OUT3) U10.20(OUT4) ; also on sheet 14
1P0V_D1_REG_ADJ: R67.2 R69.2 U10.16(FB)
1P0V_D1_REG_EN: R66.2 SW17.5 U10.11(EN)
1P0V_D1_REG_SS: C28.1 U10.15(SS)
1P0V_D1_REG_TRIM: R69.1 R601.2
1P0V_D2: C611.1 C612.1 C613.1 L7.1 R607.1 U102.1(OUT1) U102.18(OUT2) U102.19(OUT3) U102.20(OUT4) ; also on sheet 14
1P0V_D2_REG_ADJ: R607.2 R608.2 U102.16(FB)
1P0V_D2_REG_EN: R606.2 SW17.7 U102.11(EN)
1P0V_D2_REG_SS: C610.1 U102.15(SS)
1P0V_D2_REG_TRIM: R608.1 R609.2
1P5V: C32.1 C33.1 C34.1 JMP35.1 R84.1 U12.1(OUT1) U12.18(OUT2) U12.19(OUT3) U12.20(OUT4) ; also on sheet 14
1P5V_REG_EN: R83.2 SW17.9 U12.11(EN)
1P5V_REG_EN_ADJ: R84.2 R86.1 U12.16(FB)
1P5V_REG_SS: C35.1 U12.15(SS)
1P5V_REG_TRIM: R86.2 R612.2
1P8_VREG_SS: C49.1 U16.15(SS)
1P8V: C46.1 C47.1 C48.1 JMP35.3 R118.1 U16.1(OUT1) U16.18(OUT2) U16.19(OUT3) U16.20(OUT4) ; also on sheet 14
1P8V_REG_ADJ: R118.2 R120.2 U16.16(FB)
1P8V_REG_EN: R117.2 SW17.11 U16.11(EN)
1P8V_REG_TRIM: R120.1 R613.2
2P5V: C615.1 JMP77.3 R616.1 U103.5(OUT) ; also on sheet 14
2P5V_EN: R614.1 R615.2 U103.3(EN)
2P5V_LED: D100.2 R616.2
3P3V: C67.1 C68.1 C69.1 C189.1 C190.1 C275.1 C278.1 C280.1 C281.1 C283.1 JMP62.1 JMP77.1 R169.1 R241.1 R465.1 R472.1 R473.1 R476.1 R477.1 R614.2 R639.1 R641.1 R642.1 R643.1 R644.1 R645.1 R646.1 R648.1 R657.1 R658.1 U22.1(OUT1) U22.18(OUT2) U22.19(OUT3) U22.20(OUT4) U36.6(VCCB) U37.5(VDD) U41.19(VCCB) U42.27(VCCP) U42.31(VCCI) U64.19(VCCB) ; also on sheet 12 13 14
3P3V_C_REG_ADJ: R186.2 R188.2 U24.16(FB)
3P3V_C_REG_SS: C77.1 U24.15(SS)
3P3V_CLK: C74.1 C75.1 C76.1 C630.1 C631.1 C632.1 C633.1 L100.1 L101.1 L102.1 L103.1 L104.1 L105.1 L106.1 R186.1 U24.1(OUT1) U24.18(OUT2) U24.19(OUT3) U24.20(OUT4) ; also on sheet 10 14
3P3V_CLK_REG_EN: R185.2 SW17.15 U24.11(EN)
3P3V_CLK_REG_TRIM: R188.1 R610.2
3P3V_REG_EN: R168.2 SW17.13 U22.11(EN)
3P3V_REG_TRIM: R171.1 R611.2
3P3V_USB: J101.2 R639.2
3P3VREG_ADJ: R169.2 R171.2 U22.16(FB)
3P3VREG_SS: C70.1 U22.15(SS)
AMUXA: JMP48.7 R256.1 R262.1 U1.C11(AMUXA)
AMUXB: JMP48.9 R257.1 R263.1 U1.D4(AMUXB)
CHA_CLKOUTN_CONNECTOR: C196.2 ; also on sheet 15
CHA_CLKOUTP_CONNECTOR: C194.2 ; also on sheet 15
CHB_CLKOUTN_CONNECTOR: C204.2 ; also on sheet 15
CHB_CLKOUTP_CONNECTOR: C202.2 ; also on sheet 15
CLK_DVDD: C626.1 C627.1 C643.1 L105.2 U100.48(DVDD) ; also on sheet 10 14
CLK_VCC: C628.1 C629.1 C654.1 C655.1 C669.1 C670.1 L106.2 R665.1 R666.1 R669.1 R670.1 R671.1 R684.1 R685.1 R688.1 R689.1 R690.1 U104.5(VCC) U105.5(VCC) ; also on sheet 14
CLK_VDD_IN: C624.1 C625.1 C641.1 C642.1 L104.2 U100.7(VDD_PRI_REF) U100.10(VDD_SEC_REF) ; also on sheet 13 14
CLK_VDD_OUTA: C620.1 C621.1 C644.1 C645.1 C646.1 C647.1 L102.2 U100.13(VDD_Y0) U100.18(VDD_Y1) U100.27(VDD_Y4) U100.30(VDD_Y5) ; also on sheet 14
CLK_VDD_OUTB: C622.1 C623.1 C648.1 C649.1 C650.1 C651.1 L103.2 U100.19(VDD_Y2) U100.24(VDD_Y3) U100.31(VDD_Y6) U100.34(VDD_Y7) ; also on sheet 14
CLK_VDD_PLL: C616.1 C617.1 C638.1 L100.2 U100.37(VDD_PLL1) ; also on sheet 14
CLK_VDD_PLL_A: C618.1 C619.1 C639.1 C640.1 L101.2 U100.38(VDD_PLL2) U100.39(VDD_VCO) ; also on sheet 14
CLKA0N: C660.2 R677.1 U104.10(OUTN0)
CLKA0N_CON: C660.1 J102.A30
CLKA0P: C659.1 R676.1 U104.9(OUTP0)
CLKA0P_CON: C659.2 J102.A31
CLKA1N: C662.2 R679.1 U104.12(OUTN1)
CLKA1N_CON: C662.1 J102.A22
CLKA1N_IN_CON: C658.2 J102.K35 R675.1
CLKA1P: C661.1 R678.1 U104.11(OUTP1)
CLKA1P_CON: C661.2 J102.A23
CLKA1P_IN_CON: C657.2 J102.K34 R674.1
CLKA2N: C664.2 R681.1 U104.14(OUTN2)
CLKA2N_CON: C664.1 J102.A10
CLKA2P: C663.1 R680.1 U104.13(OUTP2)
CLKA2P_CON: C663.2 J102.A11
CLKA3N: C666.2 R683.1 U104.16(OUTN3)
CLKA3N_CON: C666.1 J102.A2
CLKA3P: C665.1 R682.1 U104.15(OUTP3)
CLKA3P_CON: C665.2 J102.A3
CLKA_IN_N0: C653.1 R666.2 R668.2 U104.7(INN0)
CLKA_IN_N1: C658.1 R671.2 R673.1 U104.4(INN1)
CLKA_IN_N_Y5N: C653.2 U100.29(Y5_P)
CLKA_IN_P0: C652.1 R665.2 R667.2 U104.6(INP0)
CLKA_IN_P1: C657.1 R670.2 R672.1 U104.3(INP1)
CLKA_IN_P_Y5P: C652.2 U100.28(Y5_N)
CLKA_IN_SEL: R669.2 SW18.1 U104.2(IN_SEL)
CLKB0N: C675.2 R696.1 U105.10(OUTN0)
CLKB0N_CON: C675.1 J102.A7
CLKB0P: C674.1 R695.1 U105.9(OUTP0)
CLKB0P_CON: C674.2 J102.A6
CLKB1N: C677.2 R698.1 U105.12(OUTN1)
CLKB1N_CON: C677.1 J102.A15
CLKB1N_IN_CON: C673.2 J102.A35 R694.1
CLKB1P: C676.1 R697.1 U105.11(OUTP1)
CLKB1P_CON: C676.2 J102.A14
CLKB1P_IN_CON: C672.2 J102.A34 R693.1
CLKB2N: C679.2 R700.1 U105.14(OUTN2)
CLKB2N_CON: C679.1 J102.A19
CLKB2P: C678.1 R699.1 U105.13(OUTP2)
CLKB2P_CON: C678.2 J102.A18
CLKB3N: C681.2 R702.1 U105.16(OUTN3)
CLKB3N_CON: C681.1 J102.A27
CLKB3P: C680.1 R701.1 U105.15(OUTP3)
CLKB3P_CON: C680.2 J102.A26
CLKB_IN_N0: C668.1 R685.2 R687.1 U105.7(INN0)
CLKB_IN_N1: C673.1 R690.2 R692.1 U105.4(INN1)
CLKB_IN_N_Y7N: C668.2 U100.35(Y7_P)
CLKB_IN_P0: C667.1 R684.2 R686.1 U105.6(INP0)
CLKB_IN_P1: C672.1 R689.2 R691.1 U105.3(INP1)
CLKB_IN_P_Y7P: C667.2 U100.36(Y7_N)
CLKB_IN_SEL: R688.2 SW18.3 U105.2(IN_SEL)
CLKOUTAN: C196.1 C198.1 U1.C10(CLKOUTAN)
CLKOUTAN_SMA: C198.2 J46.1
CLKOUTAP: C192.1 C194.1 U1.C9(CLKOUTAP)
CLKOUTAP_SMA: C192.2 J45.1
CLKOUTBN: C204.1 C206.1 U1.A10(CLKOUTBN)
CLKOUTBN_SMA: C206.2 J48.1
CLKOUTBP: C200.1 C202.1 U1.A9(CLKOUTBP)
CLKOUTBP_SMA: C200.2 J47.1
D12_1: D12.1 Q3.3(D)
D12_2: D12.2 R278.2
D13_1: D13.1 Q4.3(D)
D13_2: D13.2 R280.2
D14_1: D14.1 Q5.3(D)
D14_2: D14.2 R281.2
D15_1: D15.1 Q7.3(D)
D15_2: D15.2 R282.2
D16_1: D16.1 Q6.3(D)
D16_2: D16.2 R284.2
EXT_I2C_INT1: JMP102.7 R654.1
EXT_I2C_INT2: JMP102.11 R656.1
EXT_I2C_RESET1: JMP102.5 R653.1
EXT_I2C_RESET2: JMP102.9 R655.1
EXT_I2C_SCL: JMP102.1 R651.1
EXT_I2C_SDA: JMP102.3 R652.1
GPI1: U42.12(P13) U64.16(B4)
GPI1_LS: R461.2 U64.5(A4)
GPIO: R253.2 SW11.13 U1.J10(GPI0)
GPO0_LS: R286.2 U41.6(A5)
GPO1_LS: R287.2 U41.7(A6)
I2C_DIS_FET: R632.1 U42.8(P07)
I2C_DIS_FETG: Q100.1(G) R632.2
I2C_GPIO_ADDR: R648.2 SW11.19 U42.26(ADDR)
I2C_GPIO_INT: R473.2 R511.2 R650.2 U42.32(~{INT})
I2C_GPIO_RESET: R472.2 R510.2 R649.2 U42.28(~{RESET})
I2C_GPIO_SCL: R476.2 R508.2 U42.29(SCL)
I2C_GPIO_SDA: R477.2 R509.2 U42.30(SDA)
I2C_INT2_SOURCE: R650.1 R656.2 R658.2 R664.2
I2C_INT_SOURCE: R511.1 R654.2 R662.2
I2C_LOSA: R621.1 U41.18(B2)
I2C_LOSA/MDIO_C_RLY: R621.2 R623.2 U42.1(P00)
I2C_LOSA_LS: R276.2 U41.3(A2)
I2C_LOSB: R622.1 U41.17(B3)
I2C_LOSB/MDIO_B_RLY: R622.2 R624.2 U42.2(P01)
I2C_LOSB_LS: R283.2 U41.4(A3)
I2C_LS0_EN: R625.2 R627.1 R629.1 U64.10(OE)
I2C_LS1_EN: R626.2 R628.1 R630.1 U41.10(OE)
I2C_LS_EN: JMP100.1 R629.2 R630.2 R631.2 R633.1
I2C_MAIN_RESET: R466.1 U42.9(P10)
I2C_PDTRXA_N: U42.10(P11) U64.18(B2)
I2C_PDTRXA_N_LS: R459.2 U64.3(A2)
I2C_PDTRXB_N: U42.11(P12) U64.17(B3)
I2C_PDTRXB_N_LS: R460.2 U64.4(A3)
I2C_PRBS_PASS: U41.16(B4) U42.3(P02)
I2C_PRBS_PASS_LS: R285.2 U41.5(A4)
I2C_PRBSEN: U42.14(P15) U64.14(B6)
I2C_PRBSEN_LS: R463.2 U64.7(A6)
I2C_RESET2_SOURCE: R649.1 R655.2 R657.2 R663.2
I2C_RESET_SOURCE: R510.1 R653.2 R661.2
I2C_SCL_SOURCE: R508.1 R651.2 R659.2
I2C_SDA_SOURCE: R509.1 R652.2 R660.2
JTAG_LS_EN: R270.2 R647.2 U40.10(OE)
JTAG_LS_VCCB: C303.1 R268.2 R269.1 U40.19(VCCB)
JTAG_LS_VCCB_3V: JMP62.2 R269.2
LOSA: JMP48.1 R273.1 R276.1 U1.E9(LOSA)
LOSA_G: Q3.1(G) R273.2
LOSB: JMP48.3 R279.1 R283.1 U1.K8(LOSB)
LOSB_G: Q4.1(G) R279.2
LS_EN_FETD: Q100.3(D) R633.2
LS_OK_IN_A_CONNECTOR: JMP61.3 R254.2 R532.1 R619.1 U1.B10(RXCTRL_0) U42.15(P16) U64.13(B7) ; also on sheet 15
LS_OK_IN_B_CONNECTOR: JMP61.5 R255.2 R533.1 R620.1 U1.L8(RXCTRL_1) U42.16(P17) U64.12(B8) ; also on sheet 15
LS_OK_OUT_A_CONNECTOR: JMP61.4 R274.1 R286.1 U1.D9(GPO0) U41.15(B5) U42.4(P03) ; also on sheet 15
LS_OK_OUT_A_G: Q5.1(G) R274.2
LS_OK_OUT_B_CONNECTOR: JMP61.6 R277.1 R287.1 U1.H9(GPO1) U41.14(B6) U42.5(P04) ; also on sheet 15
LS_OK_OUT_B_G: Q7.1(G) R277.2
MAIN_/RST: R243.2 R259.2 U37.1(/RST)
MAIN_/RST_B: R259.1 U38.4(B2)
MAIN_/RST_C: D11.1 U38.3(C2)
MAIN_/RST_L: D11.2 R246.2
MAIN_RESET: R486.2 ; also on sheet 10
MAIN_RESET_HS: R241.2 R243.1 R244.1 R486.1 U36.4(B)
MAIN_RST: R244.2 R258.2 U37.3(RST)
MAIN_RST_B: R258.1 U38.6(B1)
MAIN_RST_C: D10.1 U38.1(C1)
MAIN_RST_DIR: R240.1 R245.2 U36.5(DIR)
MAIN_RST_L: D10.2 R242.2
MAIN_RST_SIGNAL: R465.2 R466.2 SW10.1 U37.4(/MR)
MDC: R289.1 R294.1 R297.2 R491.2 R635.2
MDC_B2B_CON: K4.4(T1) ; also on sheet 15
MDC_BYPASS: R295.2 R635.1
MDC_CON: JMP50.2 R291.1 R295.1 R299.1
MDC_DUT: R491.1 U1.J8(MDC)
MDC_HDR: JMP103.3 K2.4(T1)
MDC_LS_BY: R298.2 R636.1
MDC_OUT_POST_LS: K2.3(T2) K4.3(T2) R294.2
MDC_POST_LS: R297.1 U43.3(A2)
MDC_PRE_LS: R307.1 R308.2 R637.2 U43.18(B2)
MDC_USB: J101.12 R308.1
MDIO: R288.2 R292.1 R296.2 R451.2 R634.2
MDIO_B2B_CON: K3.3(T2) ; also on sheet 15
MDIO_B2B_R: K3.1(CTRL) K4.1(CTRL) Q103.3(D) R641.2
MDIO_B2B_R_INV: Q103.1(G) Q104.3(D) R642.2
MDIO_B2B_RELAY: Q104.1(G) R624.1 R643.2 SW11.15
MDIO_BYPASS: R293.2 R634.1
MDIO_CON: JMP50.4 R290.1 R293.1 R298.1
MDIO_CON_R: K1.1(CTRL) K2.1(CTRL) Q101.3(D) R644.2
MDIO_CON_R_INV: Q101.1(G) Q102.3(D) R645.2
MDIO_CON_RELAY: Q102.1(G) R623.1 R646.2 SW11.17
MDIO_DUT: R451.1 U1.J7(MDIO)
MDIO_HDR: JMP103.1 K1.3(T2)
MDIO_LS: C302.1 JMP77.2 R290.2 R291.2 R306.2 R307.2 U43.19(VCCB)
MDIO_LS_BY: R299.2 R637.1
MDIO_LS_EN: R305.1 R638.2 U43.10(OE)
MDIO_OUT_POST_LS: K1.4(T1) K3.4(T1) R292.2
MDIO_POST_LS: R296.1 U43.4(A3)
MDIO_PRE_LS: R306.1 R309.2 R636.2 U43.17(B3)
MDIO_USB: J101.14 R309.1
MODE_SEL/REFCLK_SEL: R250.2 R462.1 R618.1 SW11.7 U1.H10(REFCLK_SEL)
PDTRXA_N: R247.2 R459.1 SW11.1 U1.A8(~{PDTRXA_N})
PDTRXB_N: R248.2 R460.1 SW11.3 U1.J4(~{PDTRXB_N})
PRBS_PASS: JMP48.5 R275.1 R285.1 U1.J9(PRBS_PASS)
PRBS_PASS_G: Q6.1(G) R275.2
PRBSEN: R251.2 R463.1 SW11.9 U1.B9(PRBSEN)
PRI_OSC_EN: U42.6(P05) ; also on sheet 13
PRTAD0: JMP101.1 R300.2 U1.E10(PRTAD0)
PRTAD1: R301.2 SW12.7 U1.G9(PRTAD1)
PRTAD2: R302.2 SW12.5 U1.L9(PRTAD2)
PRTAD3: R303.2 SW12.3 U1.J6(PRTAD3)
PRTAD4: R304.2 SW12.1 U1.M8(PRTAD4)
REFCLK0N: C195.2 C197.1 U1.M11(REFCLK0N)
REFCLK0N_SMP: C197.2 J42.1
REFCLK0N_U0N: C195.1 R499.1 U100.25(Y4_N)
REFCLK0P: C191.1 C193.2 U1.M10(REFCLK0P)
REFCLK0P_SMP: C191.2 J41.1
REFCLK0P_U0P: C193.1 R498.1 U100.26(Y4_P)
REFCLK1N: C203.2 C205.1 U1.K10(REFCLK1N)
REFCLK1N_SMP: C205.2 J44.1
REFCLK1N_U1N: C203.1 R497.1 U100.33(Y6_N)
REFCLK1P: C199.1 C201.2 U1.K9(REFCLK1P)
REFCLK1P_SMP: C199.2 J43.1
REFCLK1P_U1P: C201.1 R496.1 U100.32(Y6_P)
REFCLK_SEL: U42.13(P14) U64.15(B5)
REFCLK_SEL_LS: R462.2 U64.6(A5)
RESET_N: JMP42.2 U1.H5(~{RESET_N})
RESET_N_LS: JMP42.1 R239.2 U36.3(A)
RXCTRL_0_LS: R532.2 U64.8(A7)
RXCTRL_1_LS: R533.2 U64.9(A8)
SEC_OSC_EN: U42.7(P06) ; also on sheet 13
SPI_CLK: J101.36 ; also on sheet 10
SPI_LE1: J101.34 ; also on sheet 10
SPI_LE2: J101.39 ; also on sheet 10
SPI_MISO: J101.40 ; also on sheet 10
SPI_MOSI: J101.38 ; also on sheet 10
ST/GPI1: R249.2 R461.1 R617.1 SW11.5 U1.M9(ST_/_GPI1)
TCK: U1.D8(TCK) U40.7(A6)
TCK_LS: JMP47.9 U40.14(B6)
TDI: U1.C8(TDI) U40.5(A4)
TDI_LS: JMP47.5 U40.16(B4)
TDO: U1.D6(TDO) U40.4(A3)
TDO_LS: JMP47.3 U40.17(B3)
TESTEN: R252.2 SW11.11 U1.L10(TESTEN)
TMS: U1.B8(TMS) U40.6(A5)
TMS_LS: JMP47.7 U40.15(B5)
TRST_N: U1.E5(TRST_N) U40.3(A2)
TRST_N_LS: JMP47.1 U40.18(B2)
USB_I2C_INT1: J101.18 R662.1
USB_I2C_RESET1: J101.20 R661.1
USB_I2C_SCL: J101.22 R659.1
USB_I2C_SDA: J101.24 R660.1
USB_INT2: J101.21 R664.1
USB_RESET2: J101.23 R663.1
VAC_REF_A: C656.2 U104.8(VAC_REF)
VAC_REF_B: C671.2 U105.8(VAC_REF)

Not connected (* = marked no-connect by the designer): J101 7* 8* 9* 10* 11* 13* 17* 19* 25* 26* 27* 28* 29* 30* 31* 32* 33* 35* 37*; J102 1(MOUNT1)* 2(MOUNT2)* 3(MOUNT3)* 4(MOUNT4)* A37* A39* C1* C3* C5* C6* C7* C8* C9* C10* C11* C12* C13* C14* C15* C16* C17* C18* C19* C20* C21* C22* C23* C24* C25* C26* C27* C28* C29* C30* C31* C32* C33* C34* C35* C36* C37* C38* C39* C40* D5* D6* D7* D8* D9* D10* D11* D12* D13* D14* D15* D16* D17* D18* D19* D20* D21* D22* D23* D24* D25* D26* D27* D28* D29* D30* D31* D32* D33* D34* D35* D36* D37* D38* D39* D40* E1* E3* E5* E6* E7* E8* E9* E10* E11* E12* E13* E14* E15* E16* E17* E18* E19* E20* E21* E22* E23* E24* E25* E26* E27* E28* E29* E30* E31* E32* E33* E34* E35* E36* E37* E38* E39* E40* F5* F6* F7* F8* F9* F10* F11* F12* F13* F14* F15* F16* F17* F18* F19* F20* F21* F22* F23* F24* F25* F26* F27* F28* F29* F30* F31* F32* F33* F34* F35* F36* F37* F38* F39* F40* G1* G3* G5* G6* G7* G8* G9* G10* G11* G12* G13* G14* G15* G16* G17* G18* G19* G20* G21* G22* G23* G24* G25* G26* G27* G28* G29* G30* G31* G32* G33* G34* G35* G36* G37* G38* G39* G40* H5* H6* H7* H8* H9* H10* H11* H12* H13* H14* H15* H16* H17* H18* H19* H20* H21* H22* H23* H24* H25* H26* H27* H28* H29* H30* H31* H32* H33* H34* H35* H36* H37* H38* H39* H40* K2* K3* K6* K7* K10* K11* K14* K15* K18* K19* K22* K23* K26* K27* K30* K31* K37* K39*; P26 2(SHUNT)*; U8 2(NC1)* 3(NC2)* 4(NC3)* 9(PG)* 13(NC4)* 14(NC5)* 17(NC6)*; U10 2(NC1)* 3(NC2)* 4(NC3)* 9(PG)* 13(NC4)* 14(NC5)* 17(NC6)*; U12 2(NC1)* 3(NC2)* 4(NC3)* 9(PG)* 13(NC4)* 14(NC5)* 17(NC6)*; U16 2(NC1)* 3(NC2)* 4(NC3)* 9(PG)* 13(NC4)* 14(NC5)* 17(NC6)*; U22 2(NC1)* 3(NC2)* 4(NC3)* 9(PG)* 13(NC4)* 14(NC5)* 17(NC6)*; U24 2(NC1)* 3(NC2)* 4(NC3)* 9(PG)* 13(NC4)* 14(NC5)* 17(NC6)*; U40 1(A1)* 8(A7)* 9(A8)* 12(B8)* 13(B7)* 20(B1)*; U41 1(A1)* 8(A7)* 9(A8)* 12(B8)* 13(B7)* 20(B1)*; U43 1(A1)* 5(A4)* 6(A5)* 7(A6)* 8(A7)* 9(A8)* 12(B8)* 13(B7)* 14(B6)* 15(B5)* 16(B4)* 20(B1)*; U64 1(A1)* 20(B1)*; U100 14(Y0_P)* 15(Y0_N)* 16(Y1_N)* 17(Y1_P)* 20(Y2_P)* 21(Y2_N)* 22(Y3_N)* 23(Y3_P)*; U101 2(NC1)* 3(NC2)* 4(NC3)* 9(PG)* 13(NC4)* 14(NC5)* 17(NC6)*; U102 2(NC1)* 3(NC2)* 4(NC3)* 9(PG)* 13(NC4)* 14(NC5)* 17(NC6)*; U103 4(NC)*

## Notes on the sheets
sheet 2
- NOTES:
  1.  PLACE NET NAMES ON ALL JUMPERS AND HEADERS.
  2.  PLACE ALL PARTS OTHER THAN SMP CONNECTORS ON A 0 OR 90 DEGREE ORIENTATION.
  3.  SERIAL DATA SHOULD BE ROUTED AS SINGLE-ENDED 50 OHM TRANSMISSION LINES ON OUTSIDE LAYERS.  ROUTING DISTANCE SHOULD BE 3 INCHES OR LESS.
  4.  USE ROGERS MATERIAL FOR OUTSIDE LAYERS AND FR4-370 MATERIAL FOR INSIDE LAYERS.
  5.  SERIAL AND REFCLK NETS MUST MATCH WITHIN +/- 0.5 MILS
  6.  MATCH DIFFERENTIAL TRACE WIDTHS OF SERIAL AND REFCLK LINES WITH SMP/SMA PADS.
- SCHEMATIC SHEET INDEX:
- SHEET 01:  TLK10081 COVER SHEET AND NOTES
  SHEET 02:  1P0V REGULATORS
  SHEET 03:  1P5V, 1P8V, 2P5V, 3P3V REGULATORS
  SHEET 04:  POWER DISTRIBUTION
  SHEET 05:  VOLTAGE MONITORING
  SHEET 06:  DEVICE POWER AND GROUND
  SHEET 07:  GLOBAL SIGNALS
  SHEET 08:  MDIO,JTAG, AND I2C INTERFACE
  SHEET 09:  CLOCKS
  SHEET 10:  CLOCK CONTROL
  SHEET 11:  CRYSTAL OSCILLATORS
  SHEET 12:  LOW SPEED DATA SIGNALS
  SHEET 13:  HIGH SPEED DATA SIGNALS
  SHEET 14:  DATA BOARD TO BOARD CONNECTOR
  SHEET 15:  CLOCK BOARD TO BOARD CONNECTOR
sheet 3
- 1.0V ANALOG REGULATOR 1
- 1.0V ANALOG REGULATOR 2
- 1.0V DIGITAL REGULATOR 2
- 1.0V DIGITAL REGULATOR 1
sheet 4
- 3.3V CLK REGULATOR
- 3.3V REGULATOR
- 1.5V REGULATOR
- 1.8V REGULATOR
- PLACE NEAR MDIO LEVEL SHIFTER (U43)
sheet 5
- PLANE FILTERING / BULK DECOUPLING
- INSTALL 0-OHM RESISTOR
- INSTALL 0-OHM RESISTOR
- INSTALL 0-OHM RESISTOR
- INSTALL 0-OHM RESISTOR
- INSTALL 0-OHM RESISTOR
- INSTALL 0-OHM RESISTOR
- INSTALL 0-OHM RESISTOR
- INSTALL 0-OHM RESISTOR
- INSTALL 0-OHM RESISTOR
- NOTE:  PLACE GND BANANA JACKS 750 MIL
  CENTER TO CENTER SPACING WITH A POWER
  BANANA JACK LOCATED BETWEEN TWO POWER
  JACKS AND OFFSET DIAGONALLY.
- INSTALL 0-OHM RESISTOR
- INSTALL 0-OHM RESISTOR
sheet 6
- NOTES:
  DECOUPLLING GENERAL GUIDELINES:
     1.  PLACE CAPACITORS SUCH THAT SMALLER VALUE CAPACITORS ARE NEARER THE DUT AND THEN SUCCESSIVELY PLACE LARGER VALUE CAPACITORS AS YOU MOVE
  AWAY FROM THE DUT.
     2.  PLACE CAPACITORS NEAR VIAS AND CONNECTORS.  THESE CAPACITORS SHOULD DECOUPLE THE DRIVER SUPPLY TO THE GROUND PLANE.  IF A SIGNAL IS
  REFERENCED TO A POWER PLANE AND THIS POWER PLANE IS NOT ASSOCIATED WITH THE DRIVER SUPPLY, THEN THIS PLANE SHOULD ALSO BE DECOUPLED TO GROUND
  NEAR ALL ASSOCIATED VIAS AND CONNECTORS.
- TLK10081 DEVICE POWER / LOCAL DECOUPLING
- NOTE:  PLACE CAPACITORS NEAR
  TLK10XXX DEVICE
- NOTE:  PLACE CAPACITORS
  NEAR TLK10XXX DEVICE
- CDCM6208 DEVICE POWER / LOCAL DECOUPLING
- NOTE:  PLACE CAPACITORS NEAR
  TLK10XXX DEVICE
- NOTE:  PLACE
  CAPACITORS NEAR
  TLK10XXX DEVICE
- NOTE:  PLACE CAPACITORS NEAR
  CDCM6208 DEVICE
- NOTE:  PLACE CAPACITORS NEAR
  TLK10XXX DEVICE
- NOTE:  PLACE
  CAPACITORS NEAR
  TLK10XXX DEVICE
- NOTE:  PLACE CAPACITORS NEAR
  CDCM6208 DEVICE
- NOTE:  PLACE CAPACITORS NEAR
  CDCM6208 DEVICE
- NOTE:  PLACE
  CAPACITORS NEAR
  TLK10XXX DEVICE
- NOTE:  PLACE CAPACITORS NEAR
  TLK10XXX DEVICE
- NOTE:  PLACE CAPACITORS NEAR
  CDCM6208 DEVICE
- NOTE:  PLACE
  CAPACITORS NEAR
  TLK10XXX DEVICE
- TLK10081 DEVICE GROUND
- NOTE:  PLACE CAPACITORS NEAR
  CDCM6208 DEVICE
- NOTE:  PLACE CAPACITORS NEAR
  CDCM6208 DEVICE
- CDCM6208 DEVICE GROUND
sheet 7
- VOLTAGE SUPERVISOR
  AND RESET MONITOR
- MAIN RESET
  PUSHBUTTON
- BI-DIRECTIONAL
  LEVEL SHIFTER
- I2C-TO-GPIO OUTPUT PINS
- BI-DIRECTIONAL
  LEVEL SHIFTER
- I2C DISABLE HEADER
- PIN M9 AND H10 ASSIGNMENT:
  TLK10081:
  M9   =GPI1
  H10 = REFCLK_SEL
- OVERLAP
  RESISTOR
  PADS
- I2C-TO-GPIO INPUT PINS
sheet 8
- MDIO INTERFACE
- DO NOT
  OVERLAP
  RESISTOR
  PADS
- OVERLAP
  RESISTOR PADS
  R296, R297,
  R634, R635
- OVERLAP RESISTOR
  PADS R293, R295,
  R298, R299
- MDIO BUS OUTPUT
  CONNECTOR
  (LEVEL SHIFTED)
- USB INTERFACE
- PRTAD ADDRESS
- OVERLAP
  RESISTOR PADS
  R308, R309,
  R636, R637
- BI-DIRECTIONAL
  LEVEL SHIFTER
- SPI CONTROL
  INTERFACE
- FOR USE WITH CLOCK CONFIGURATION
- I2C BUS CONNECTOR
- JTAG
  INTERFACE
- USB I2C BUS
- I2C-TO-GPIO CONTROL PINS
  I2C DEVICE ADDRESS 0x22 OR 0x23
- BI-DIRECTIONAL
  LEVEL SHIFTER
- DO NOT OVERLAP 0-OHM RESISTOR PADS.  PLACE
  0-OHM RESISTORS AS CLOSE TOGETHER AS
  POSSIBLE AND AS CLOSE TO THE TCA6424 DEVICE
  TO MINIMIZE THE  STUBS ON THE I2C BUS.
sheet 9
- NOTE:
     1.  MATCH REFCLK0/1_P/N AND CLKOUT0/1_P/N TRACE LENGTHS TO EACHOTHER
- OVERLAP CAPACITOR
  PADS C191, C193
- OVERLAP CAPACITOR
  PADS C195, C197
- OVERLAP CAPACITOR
  PADS C199, C201
- OVERLAP CAPACITOR
  PADS C203, C205
- OVERLAP CAPACITOR
  PADS C192, C194
- OVERLAP CAPACITOR
  PADS C196, C198
- OVERLAP CAPACITOR
  PADS C200, C202
- OVERLAP CAPACITOR
  PADS C204, C206
